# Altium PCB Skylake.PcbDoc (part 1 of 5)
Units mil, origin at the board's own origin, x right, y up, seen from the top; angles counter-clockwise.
Board outline 4000 x 4000 mil, 8 copper layers (TOP LAYER, GND1#2, SIG1#3, SIG2#4, GND2#5, SIG3#6, GND3#7, BOTTOM LAYER), stack 132.6 mil thick; 343 components, 142 nets, 972 pads, 752 vias.
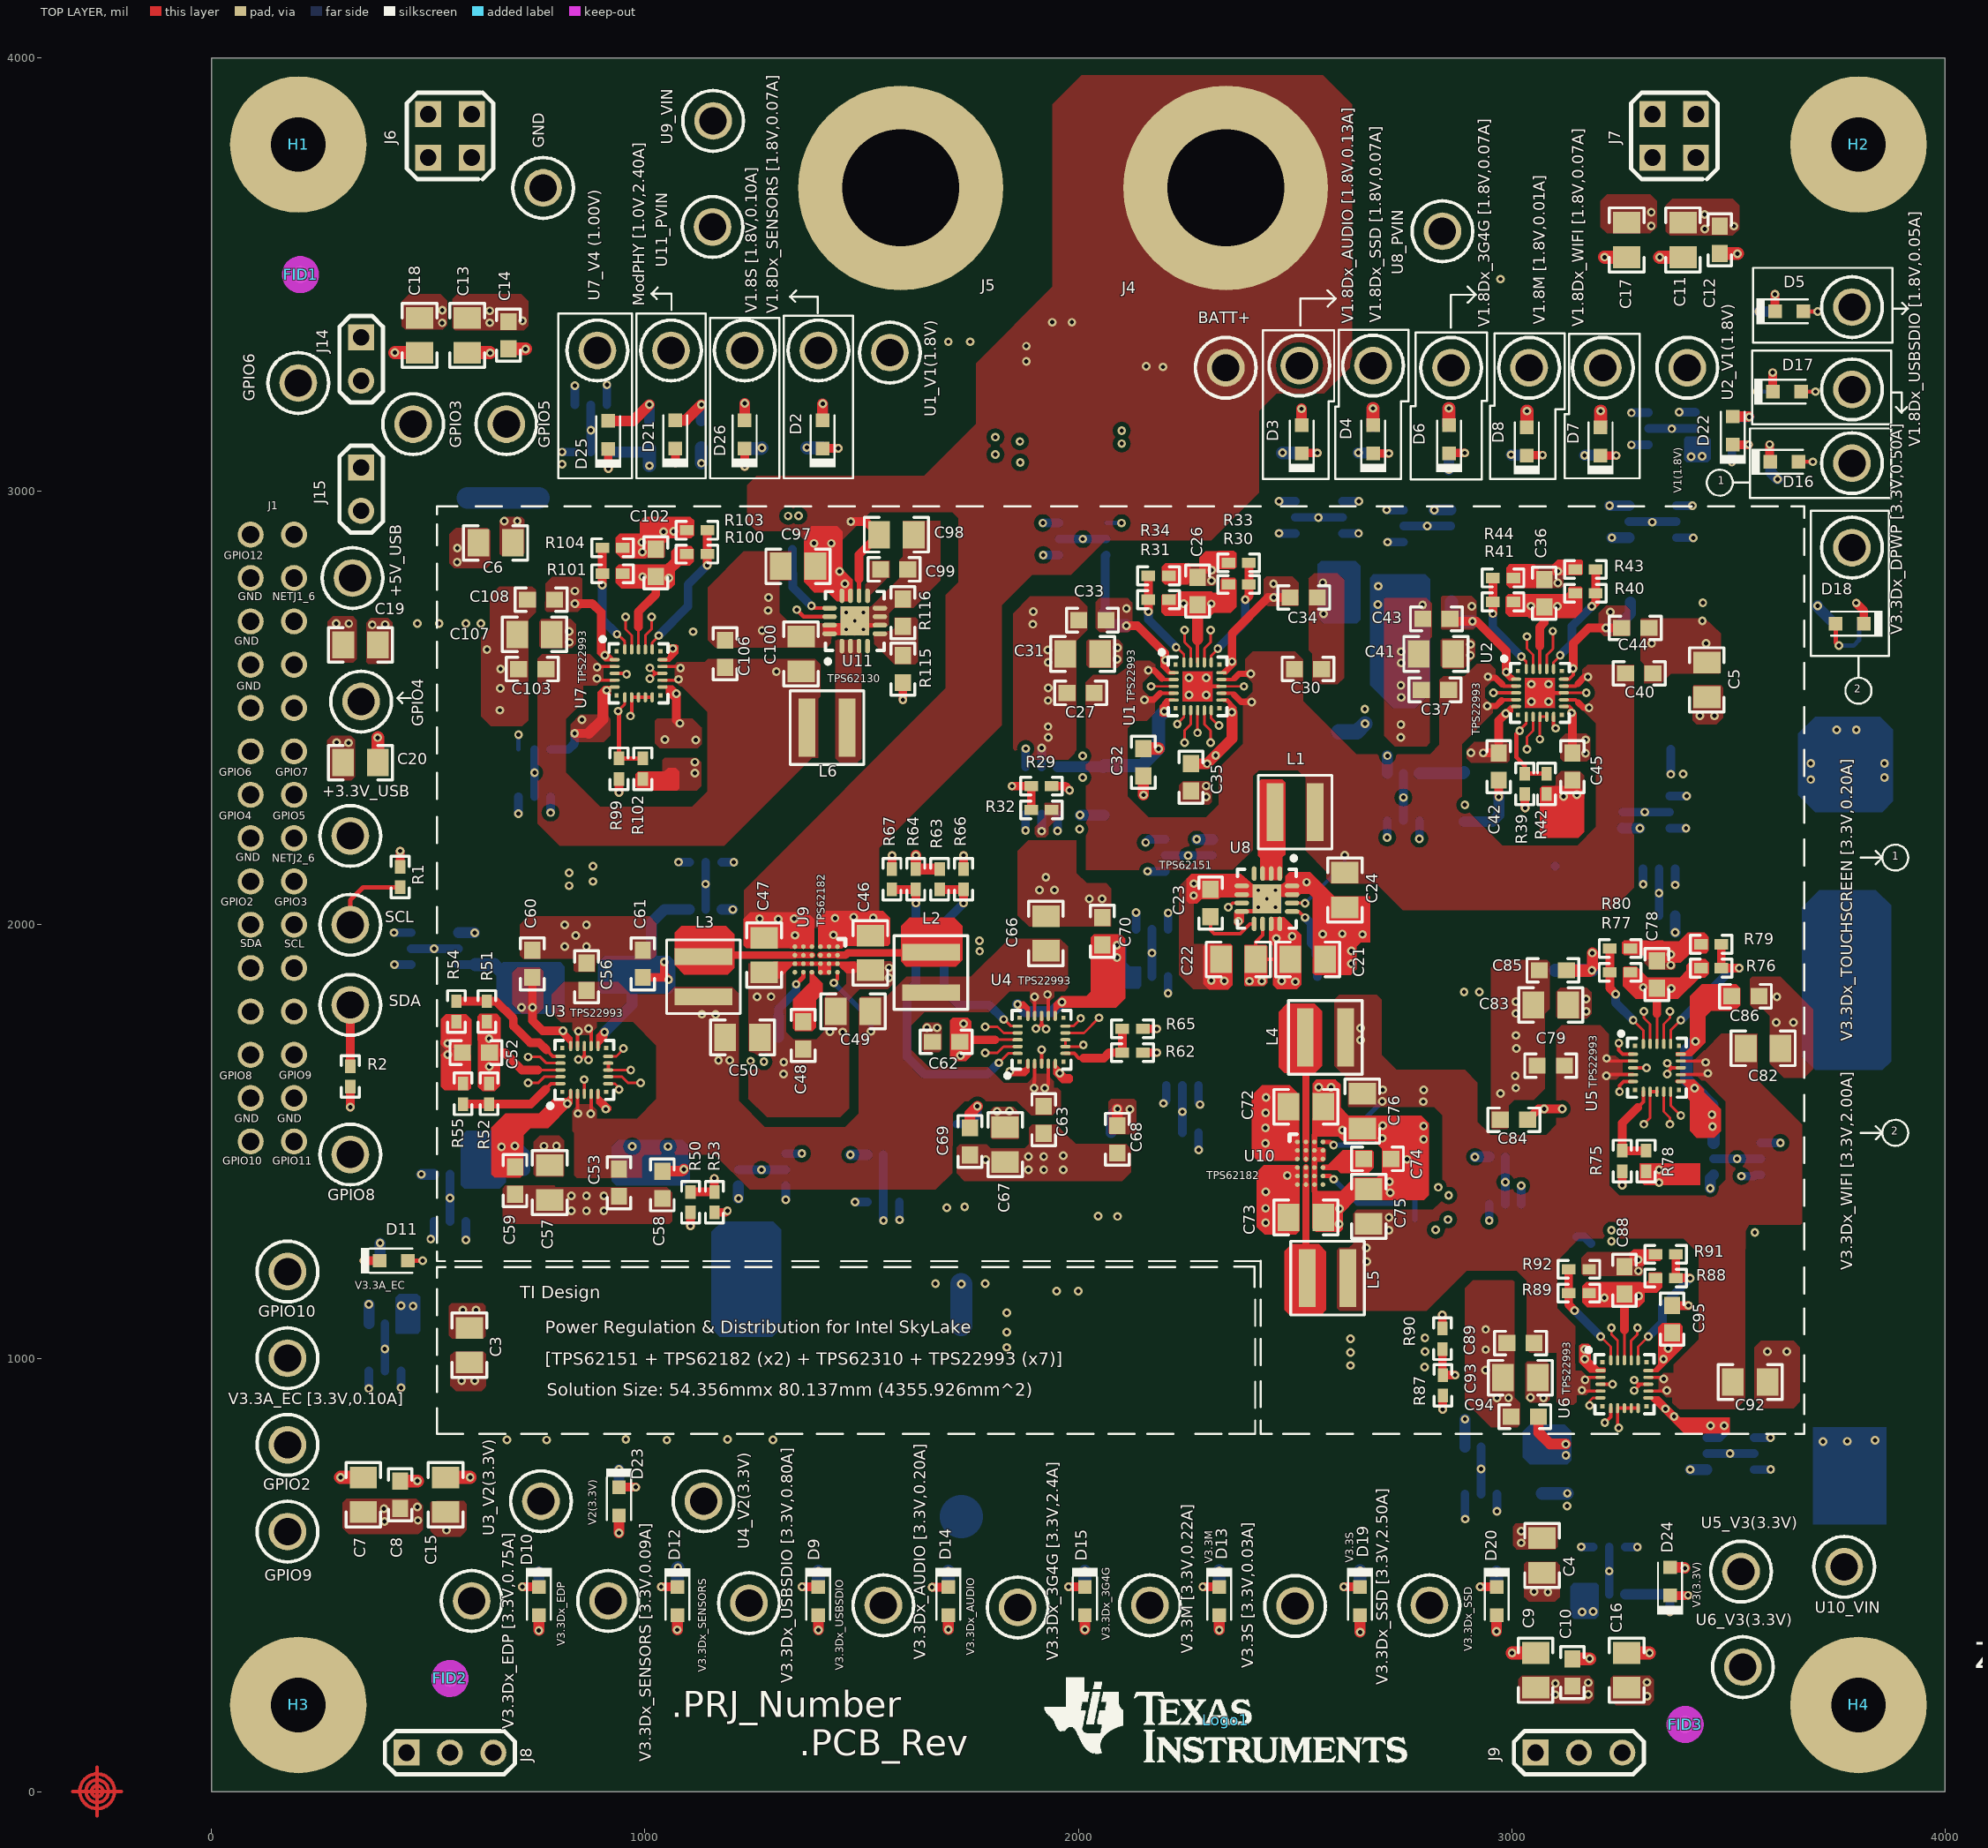
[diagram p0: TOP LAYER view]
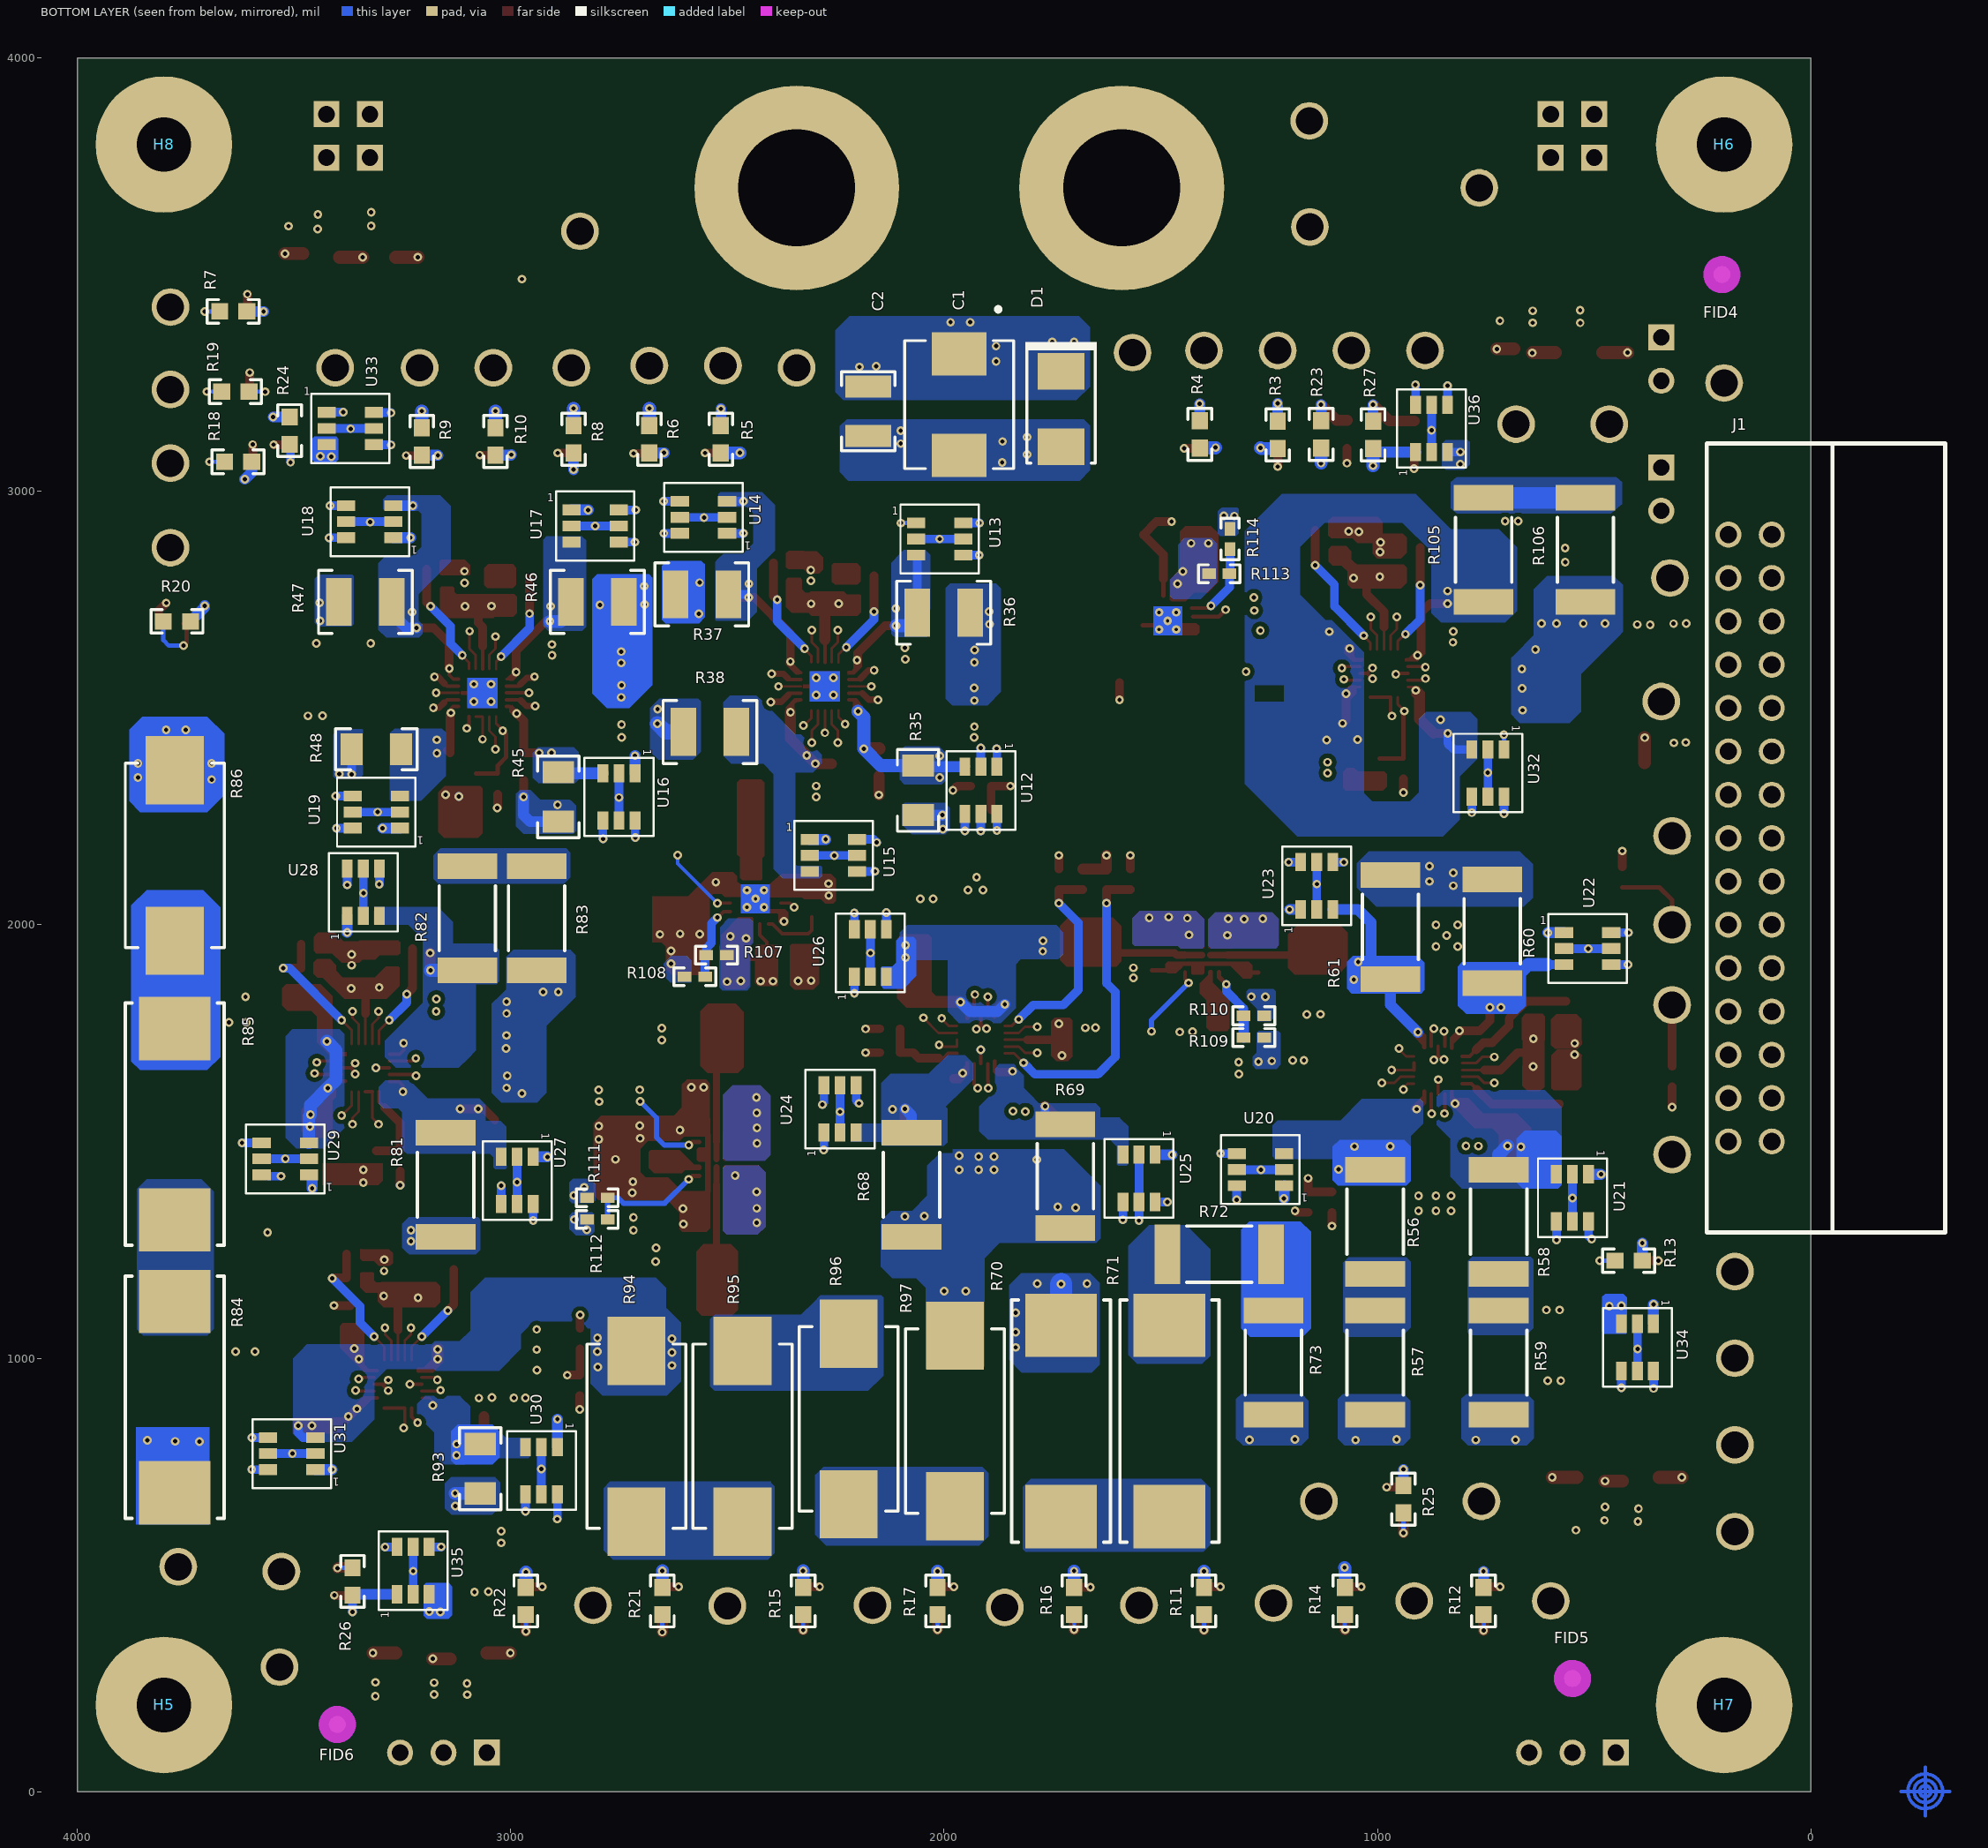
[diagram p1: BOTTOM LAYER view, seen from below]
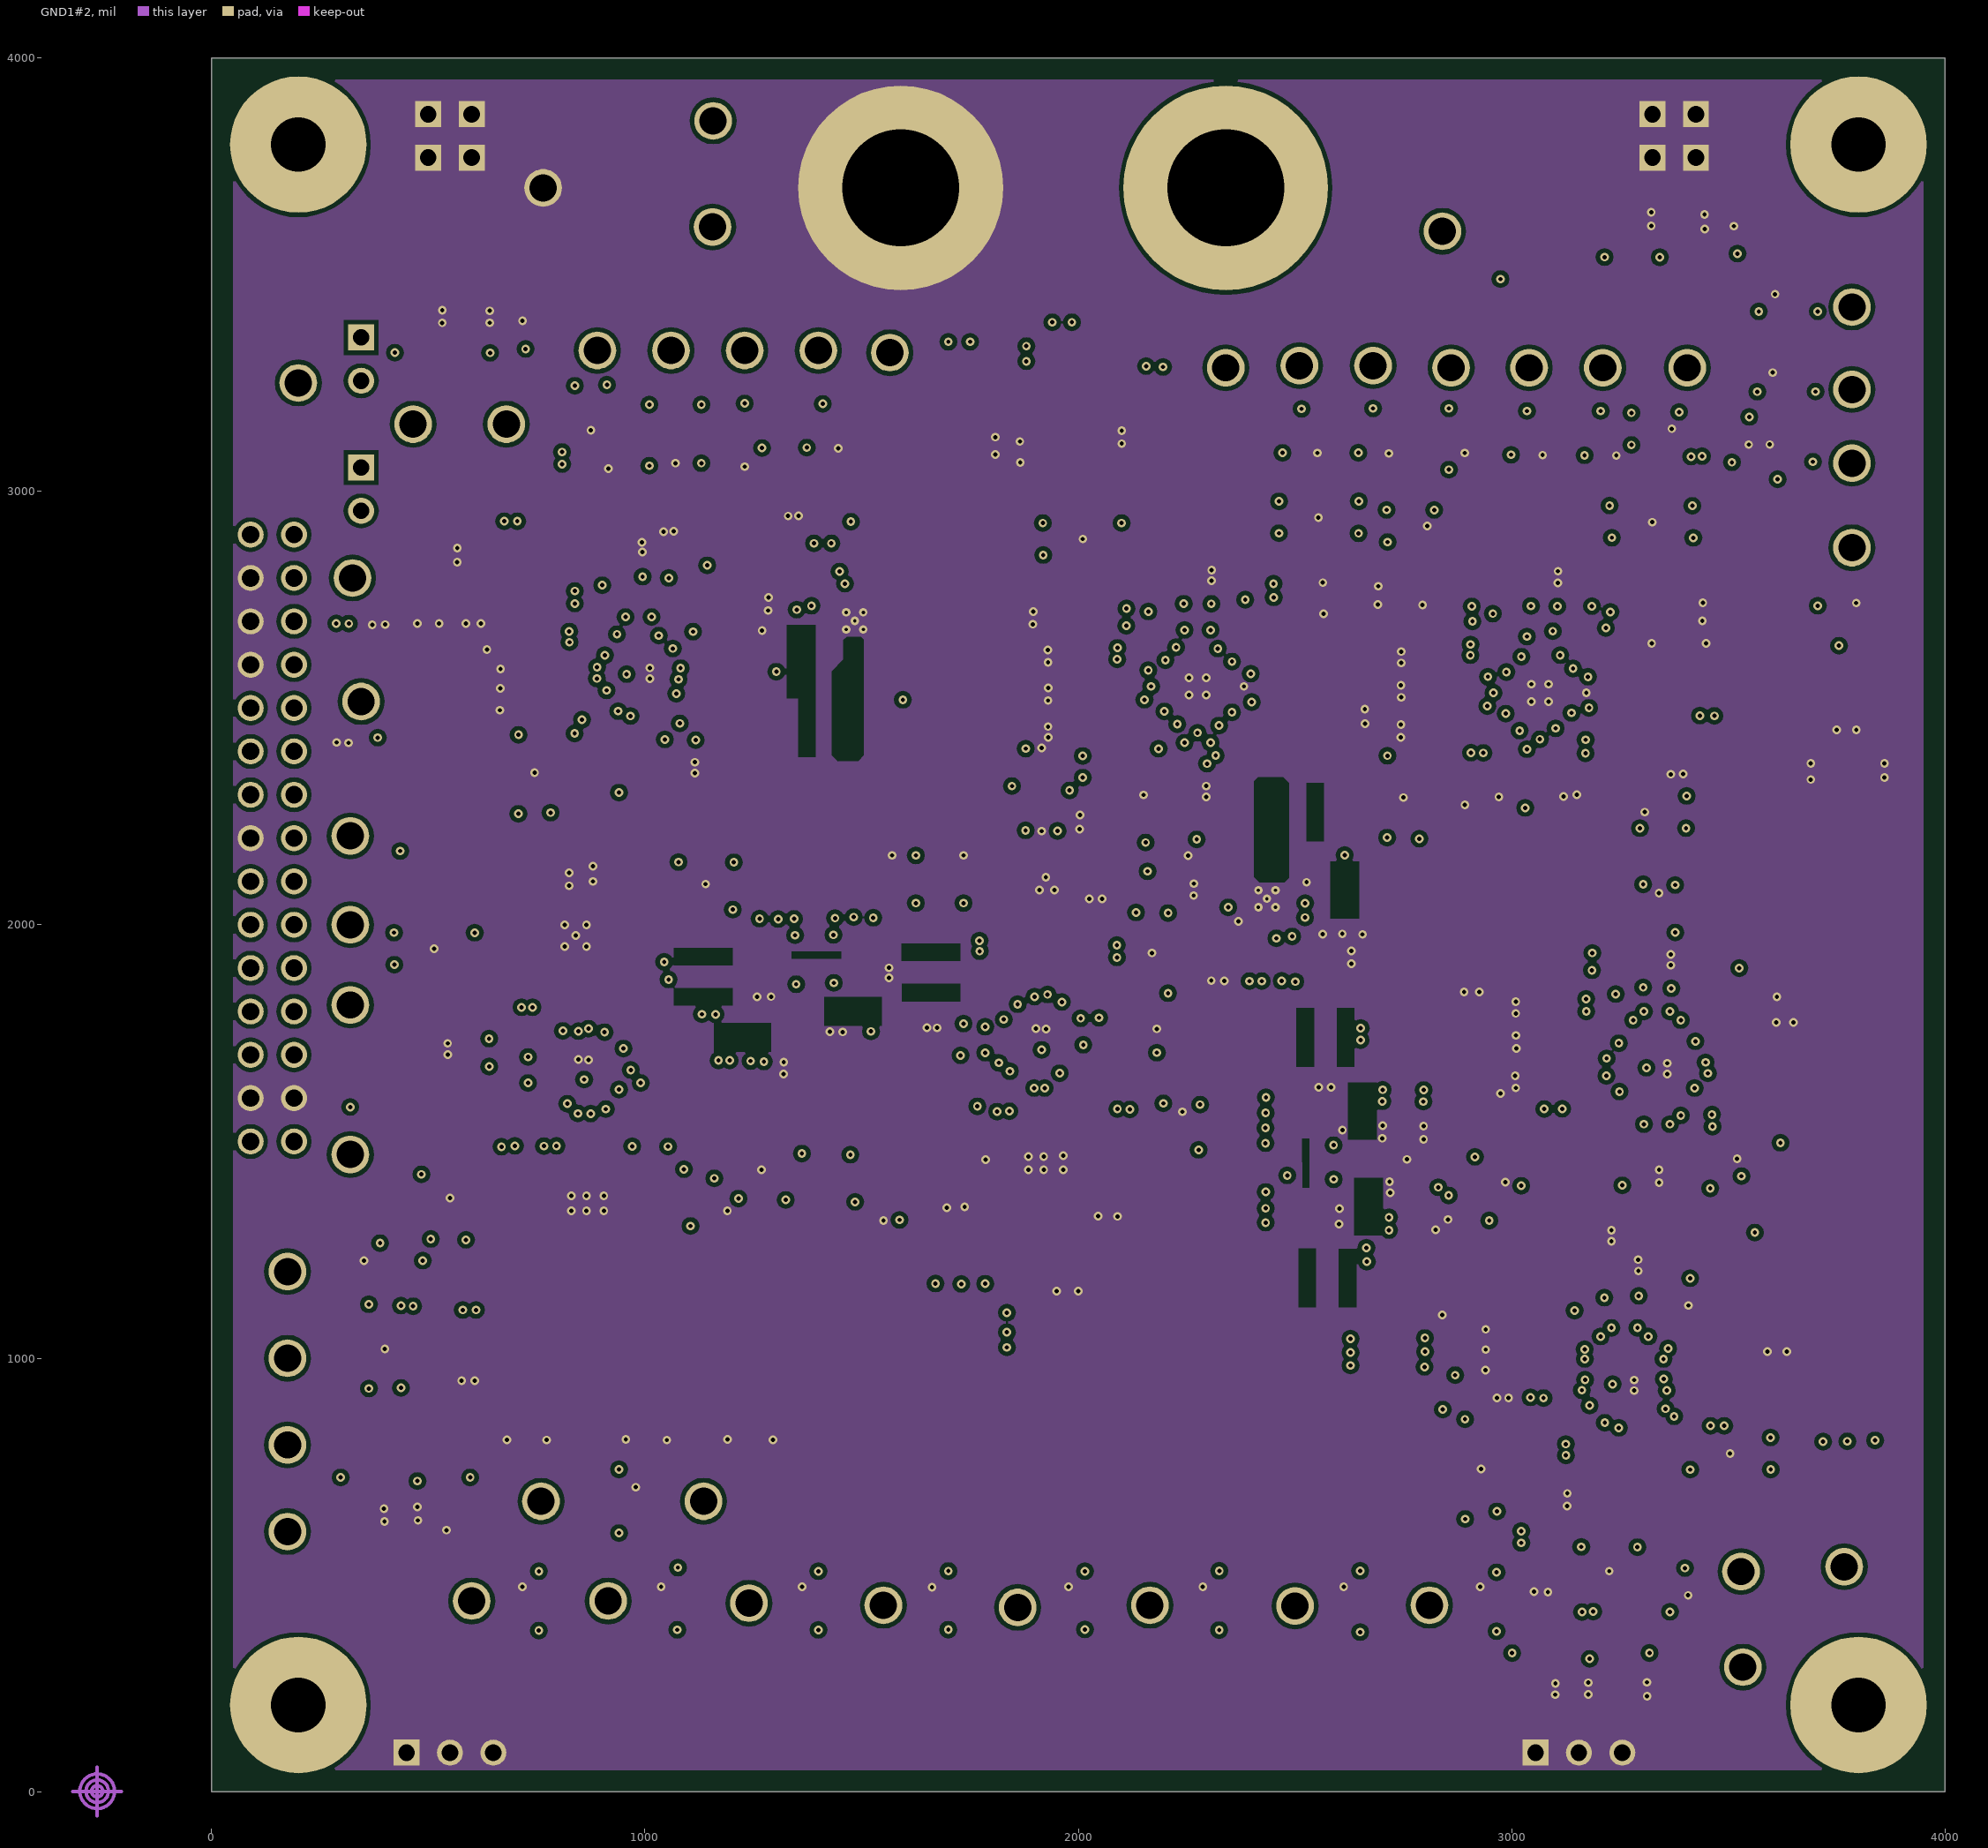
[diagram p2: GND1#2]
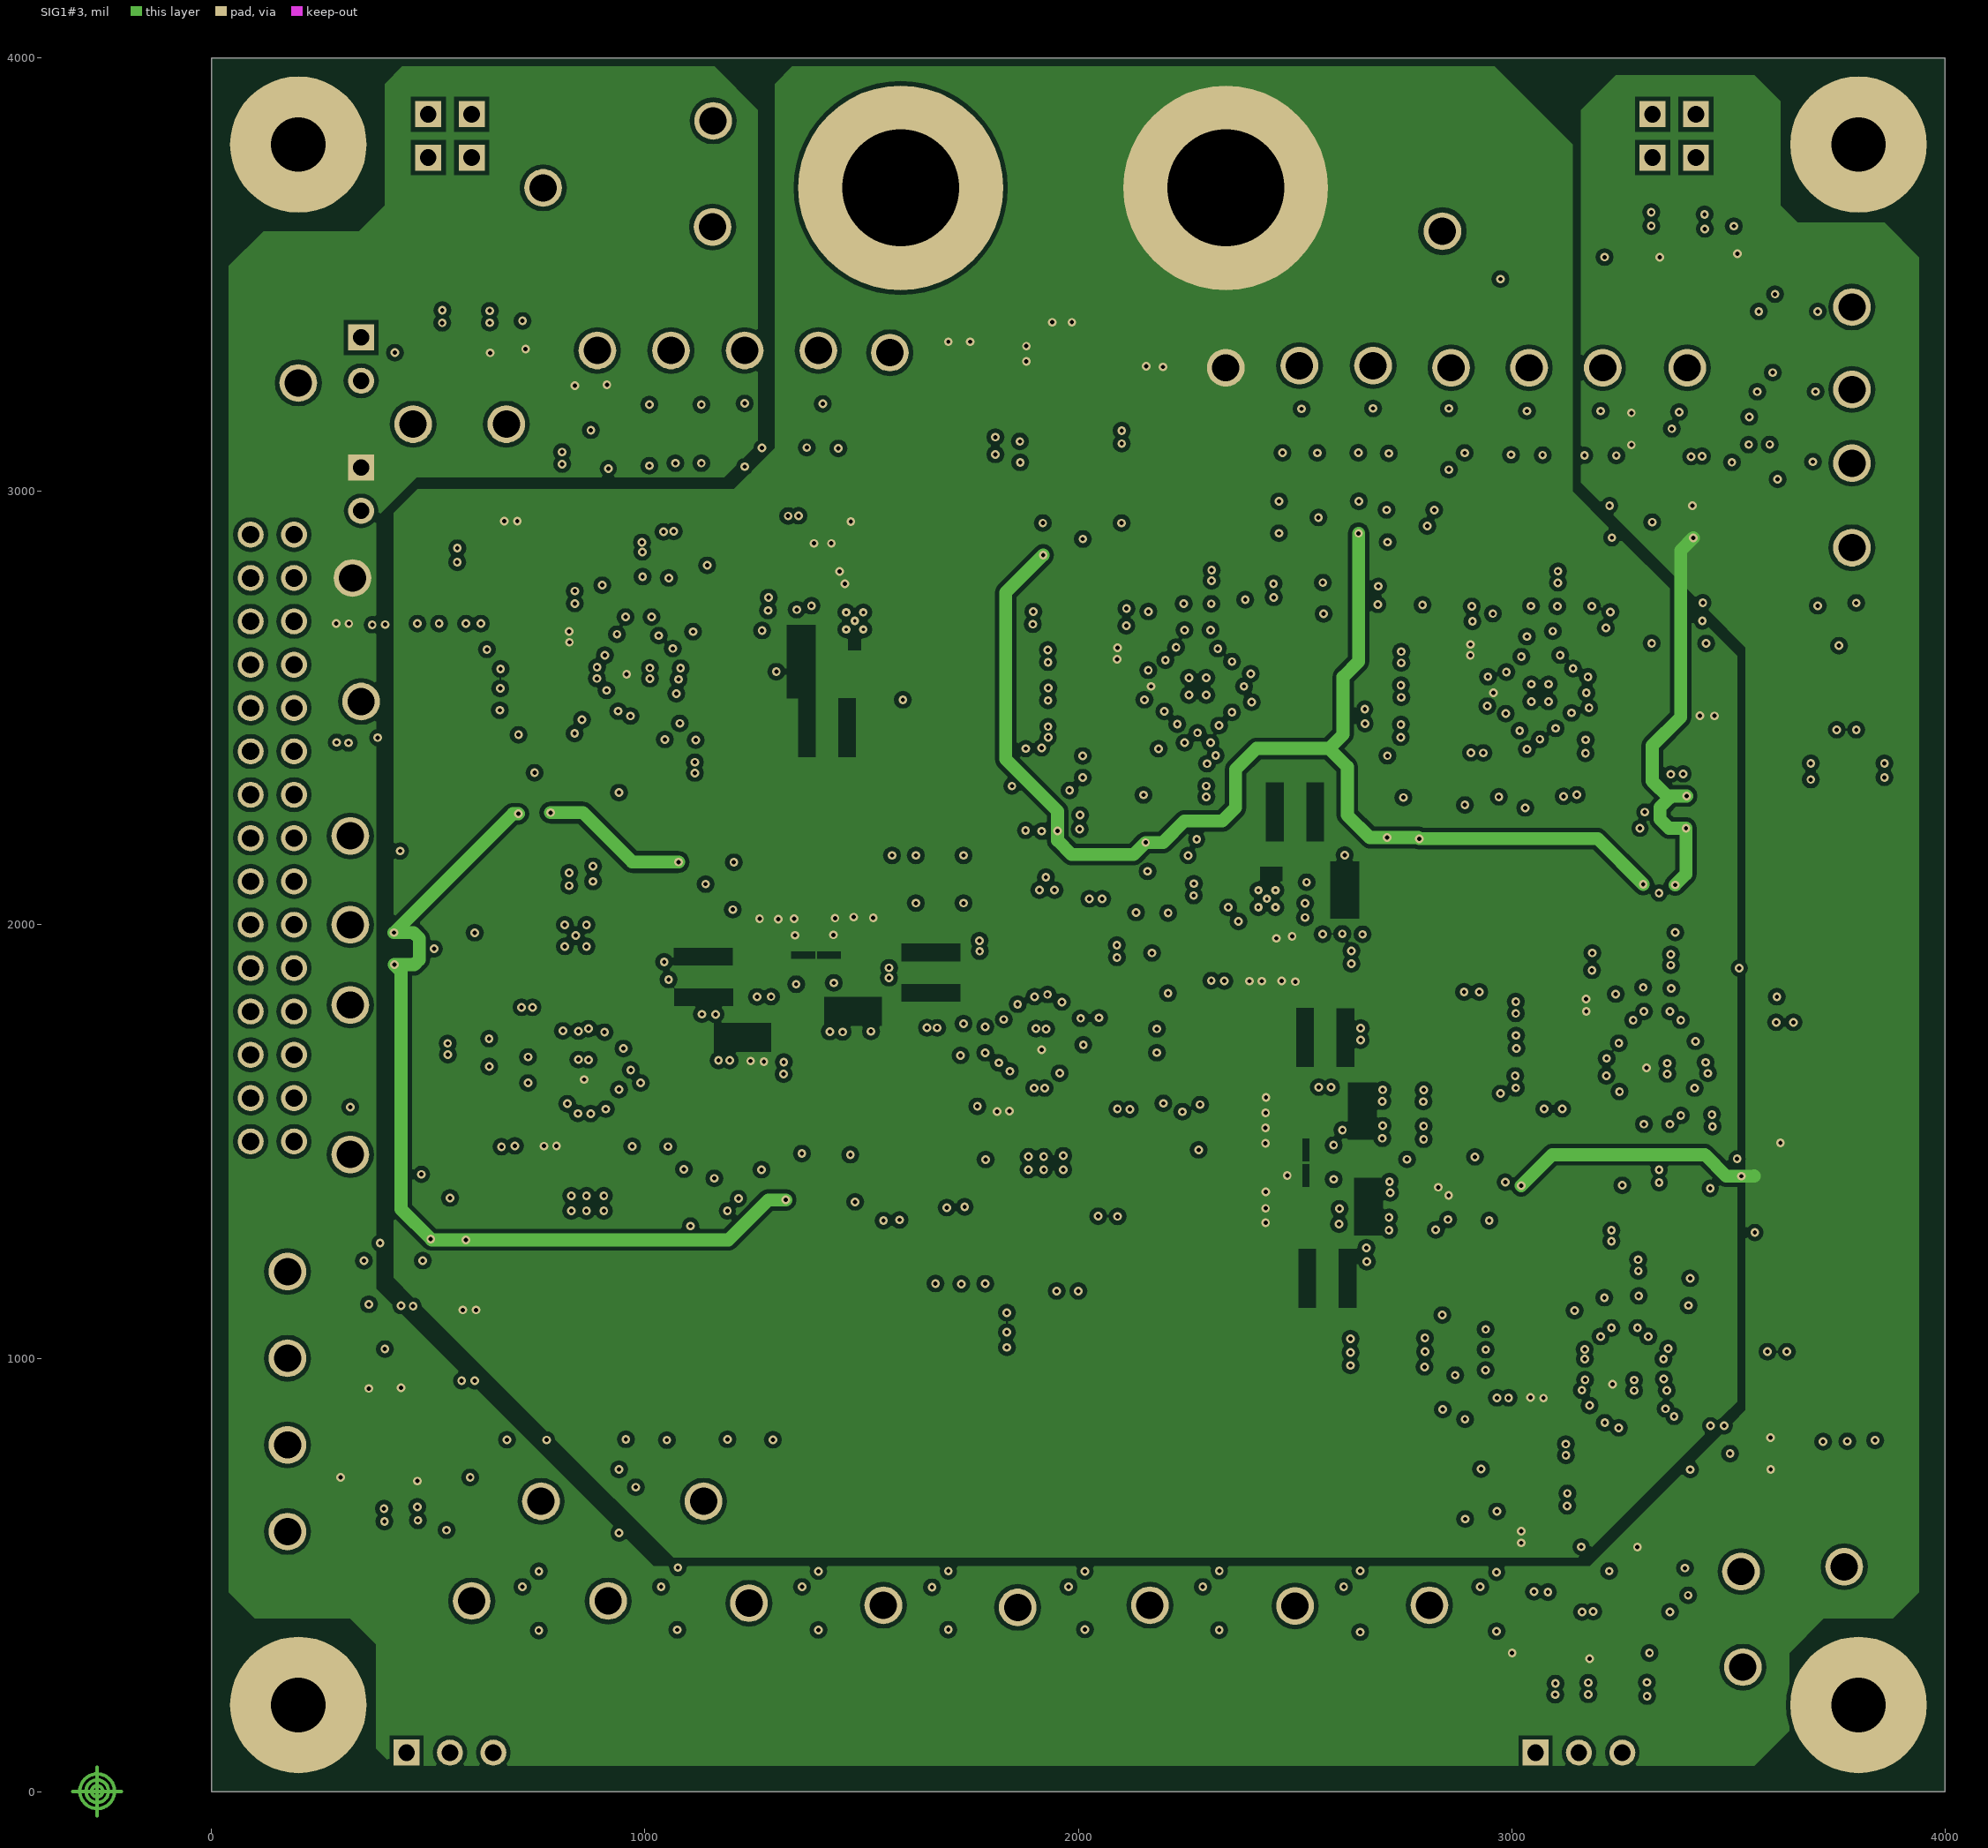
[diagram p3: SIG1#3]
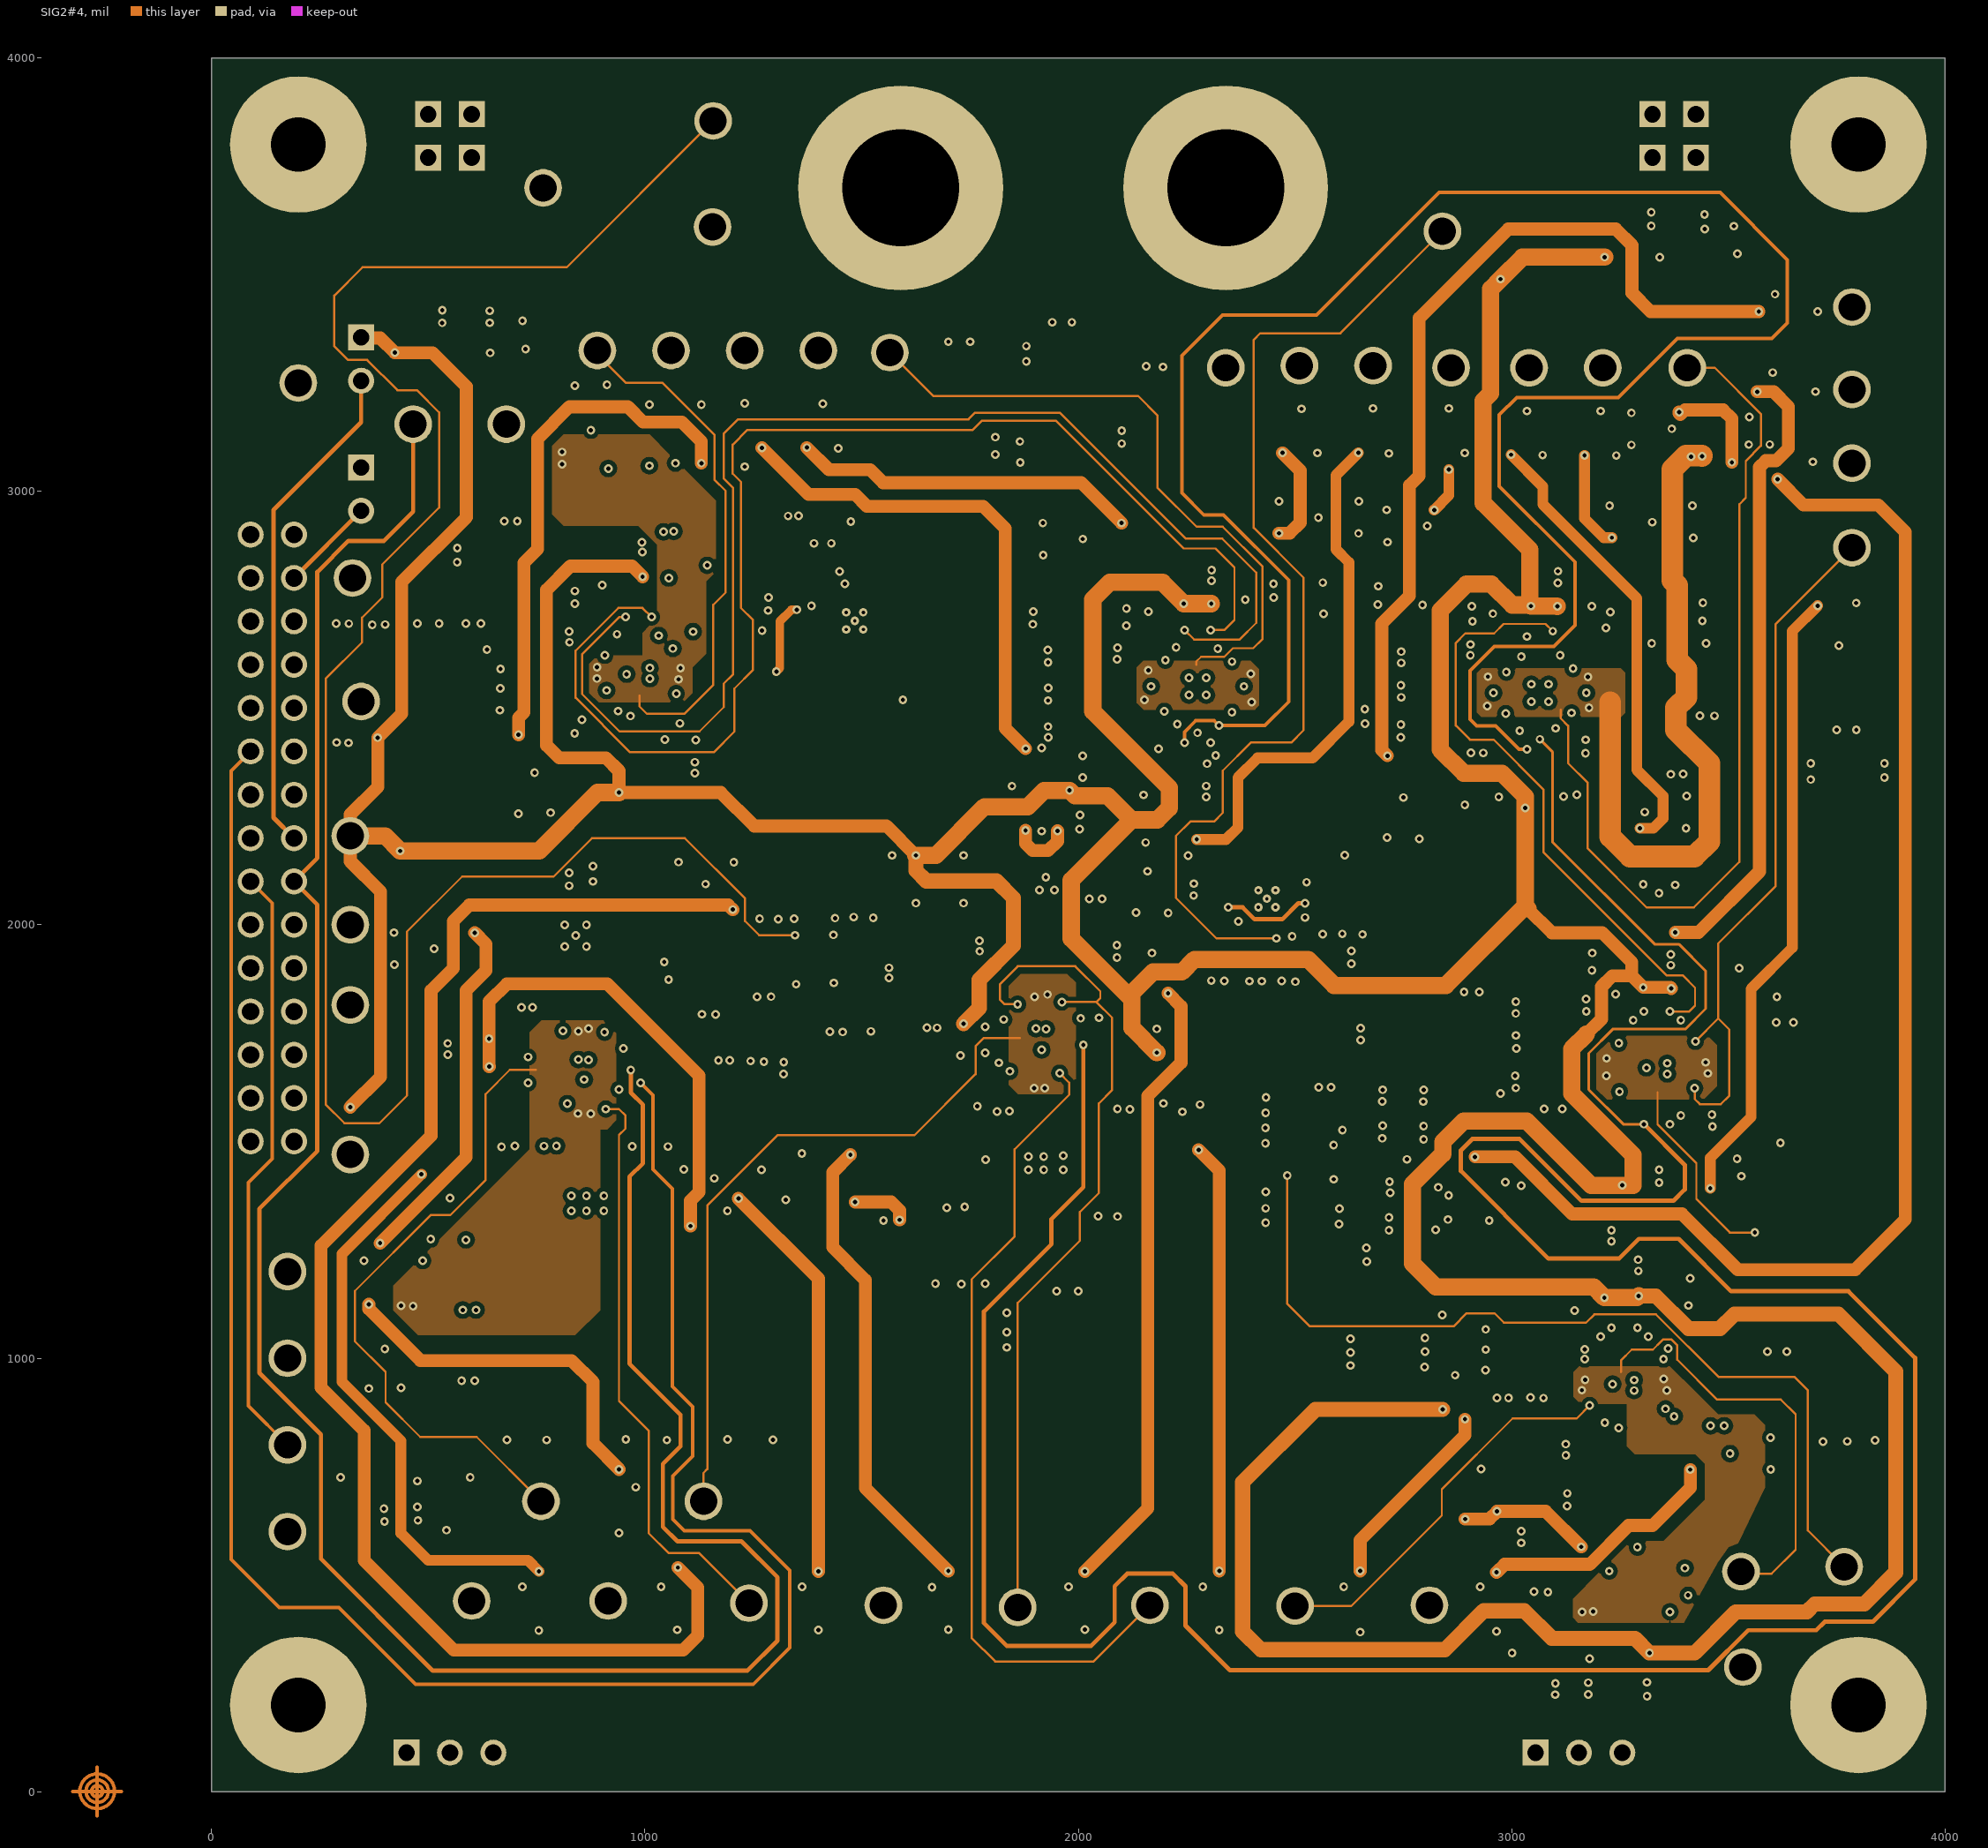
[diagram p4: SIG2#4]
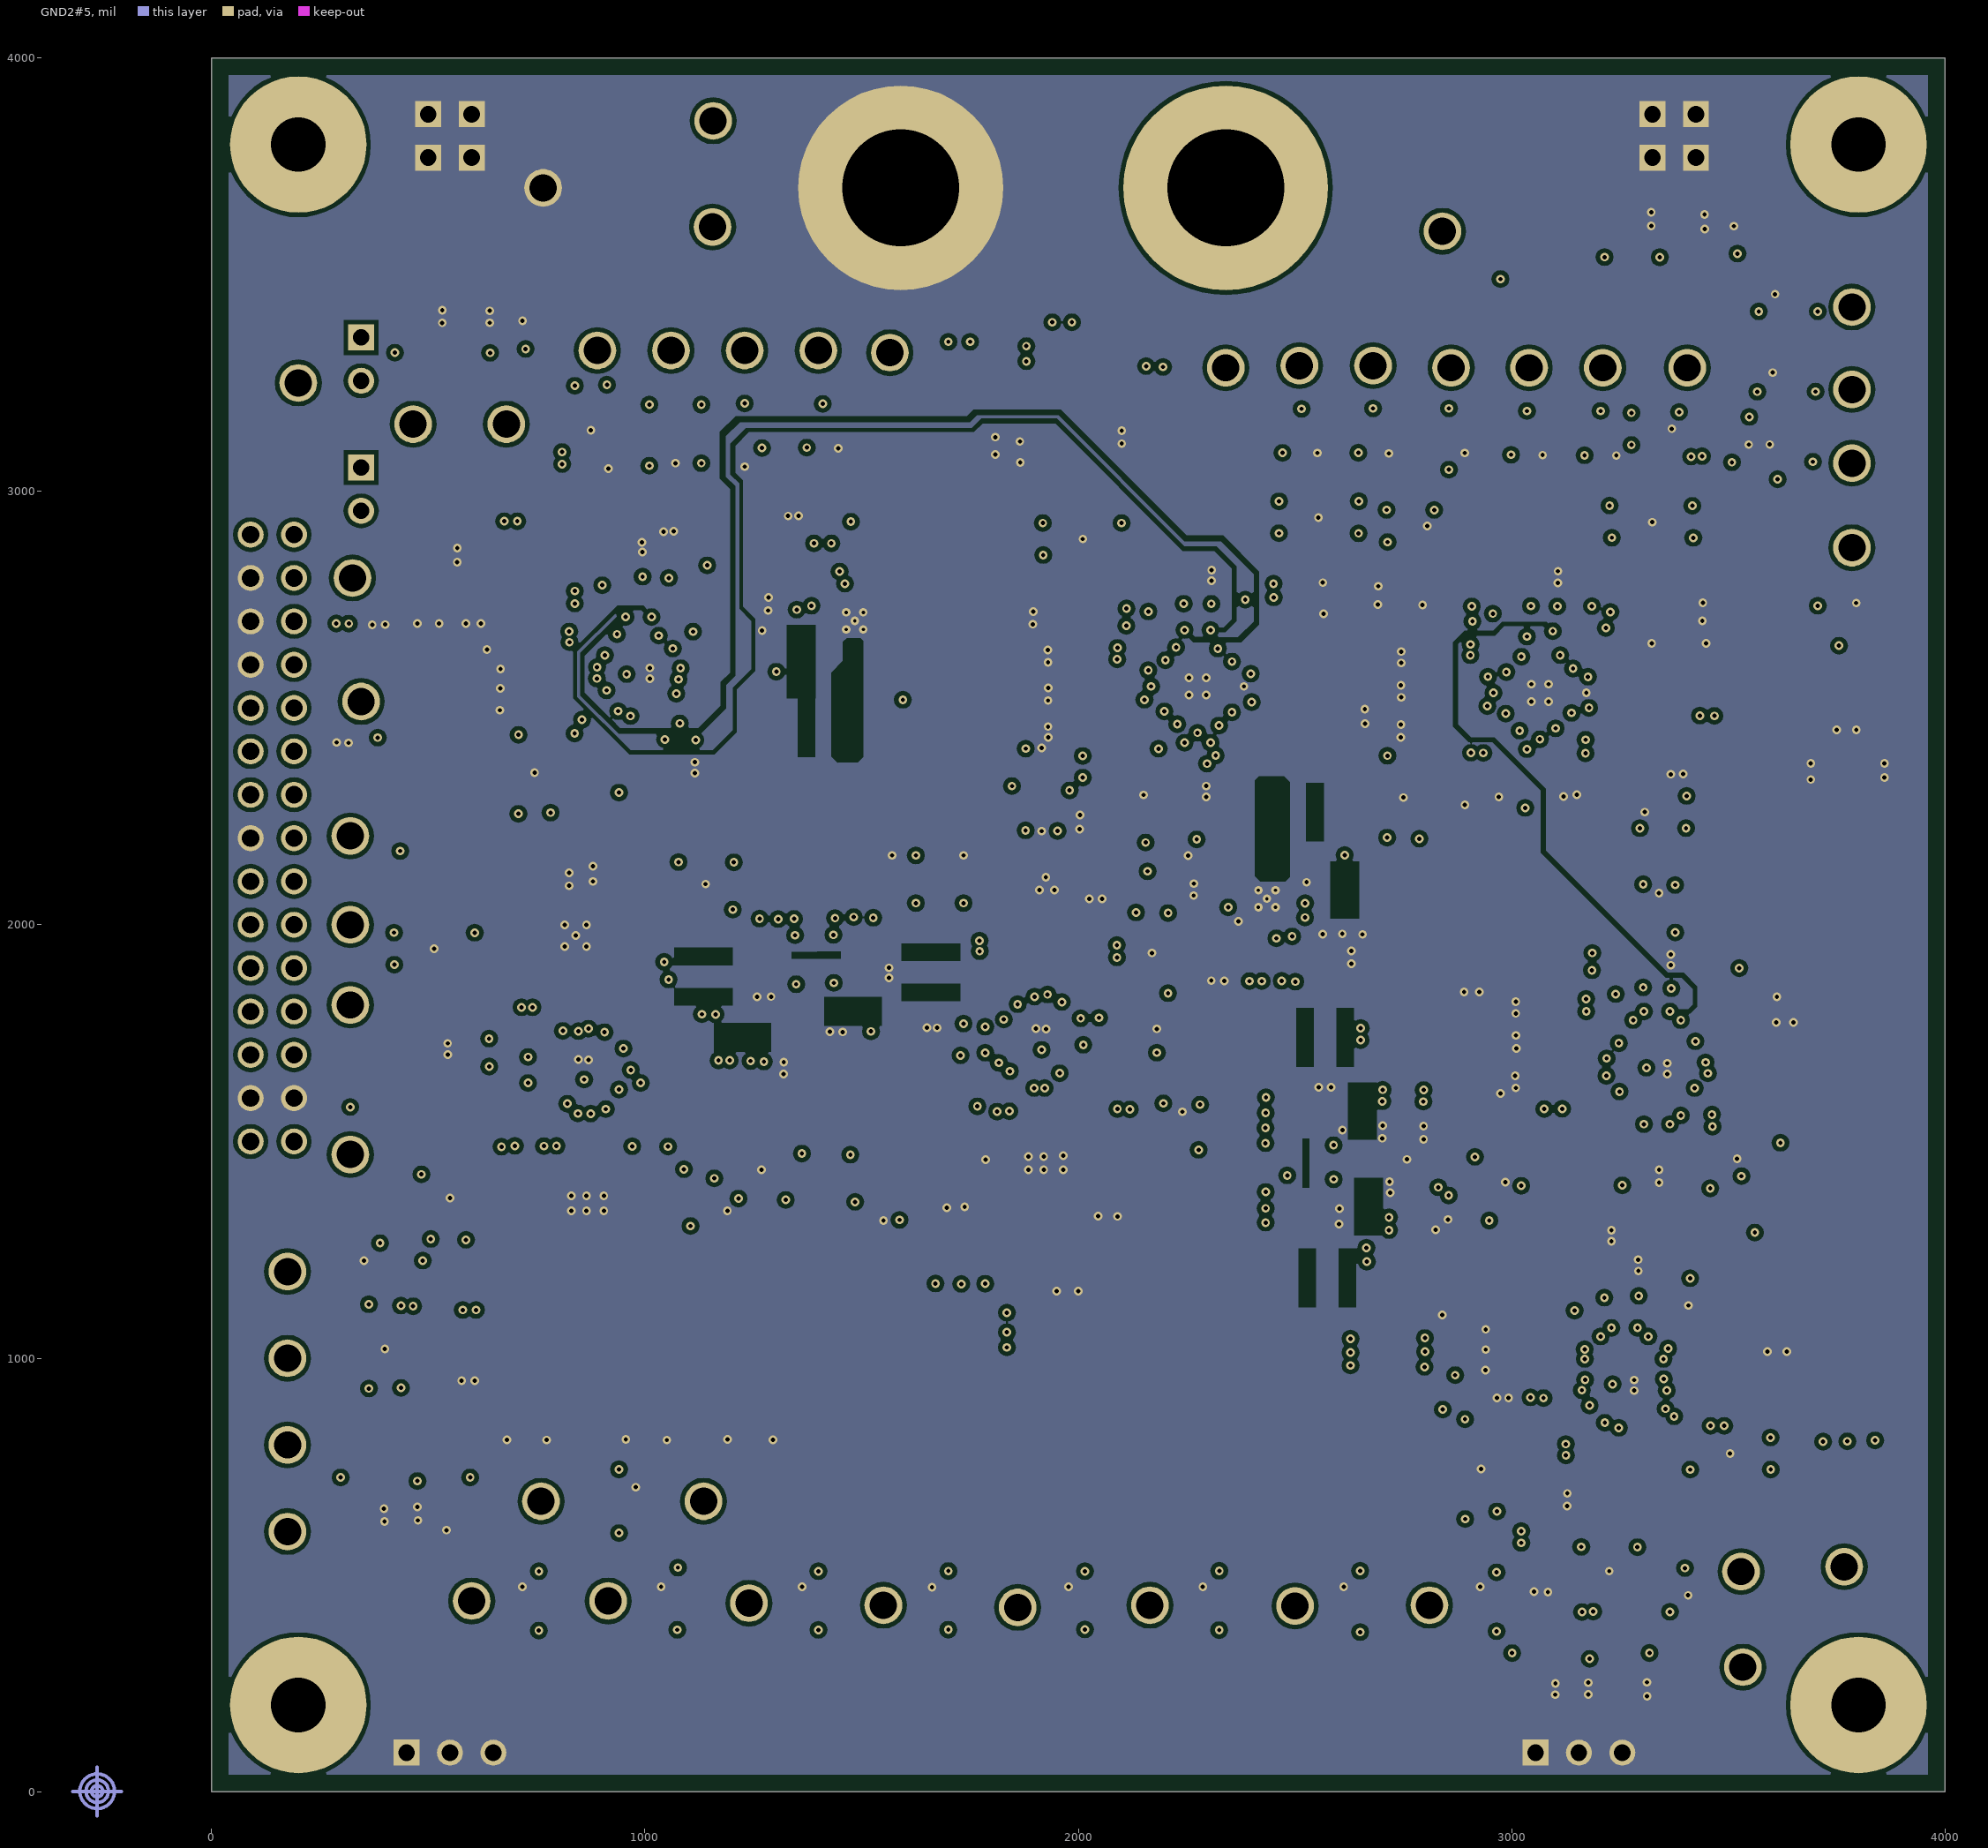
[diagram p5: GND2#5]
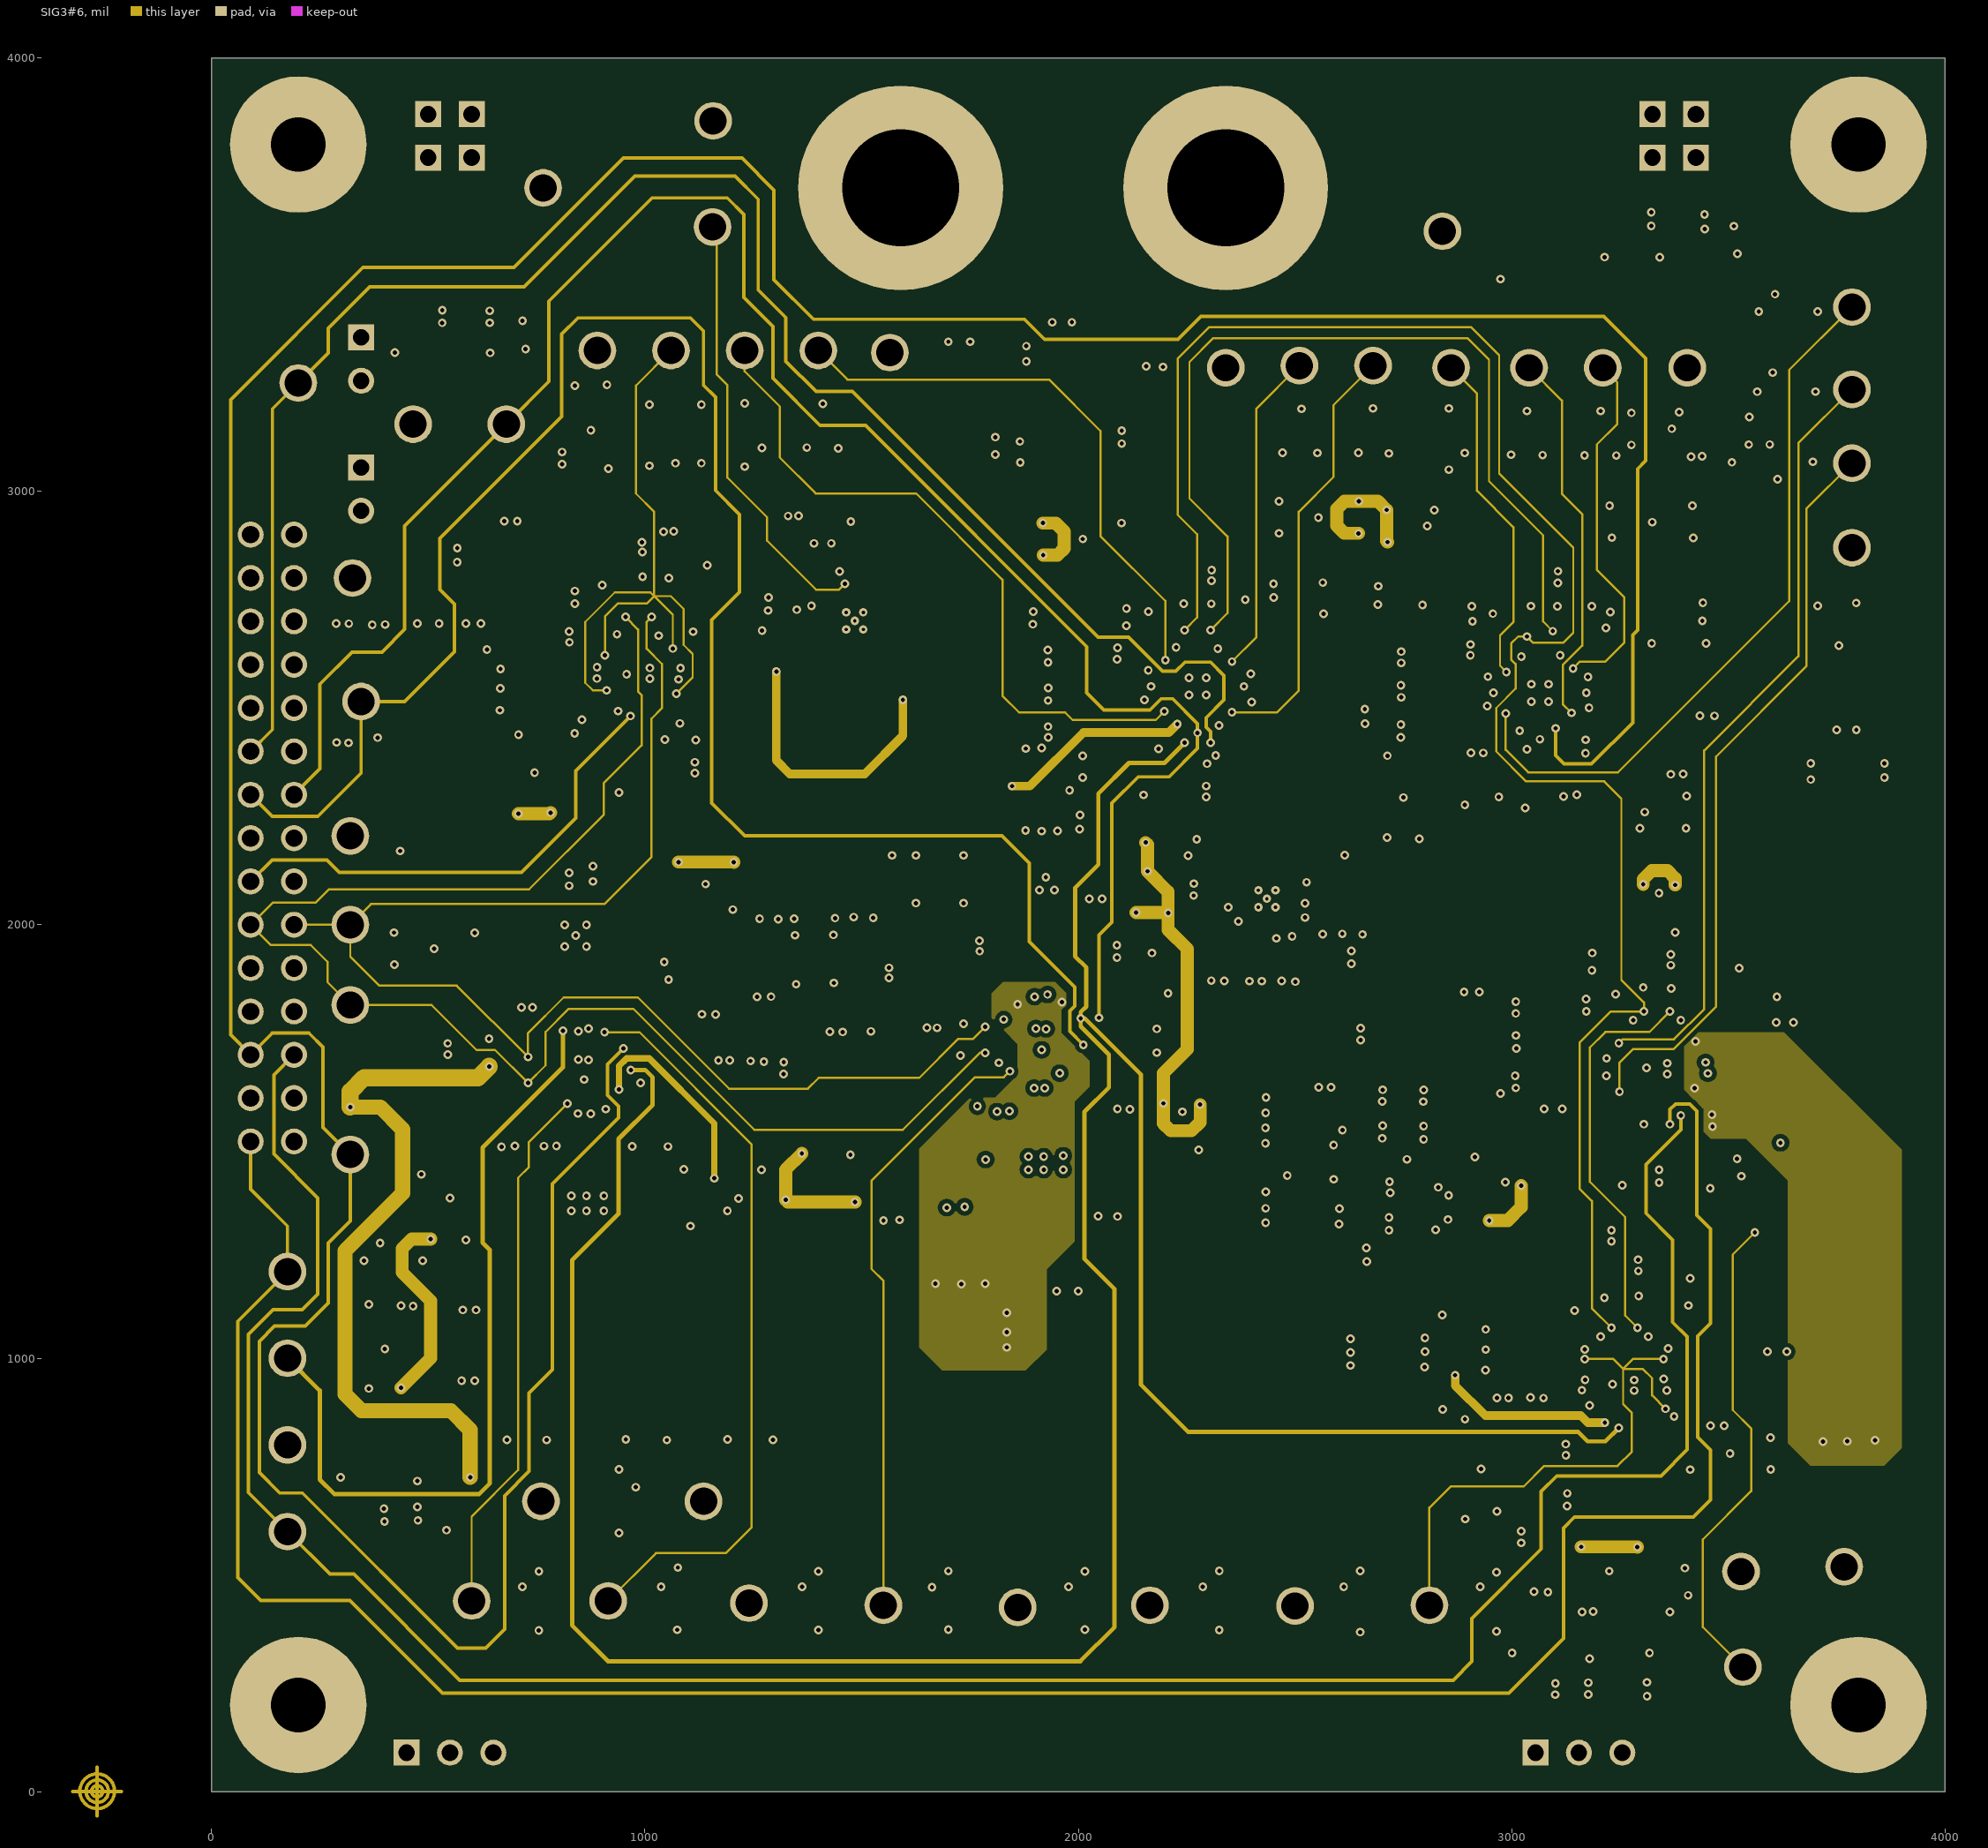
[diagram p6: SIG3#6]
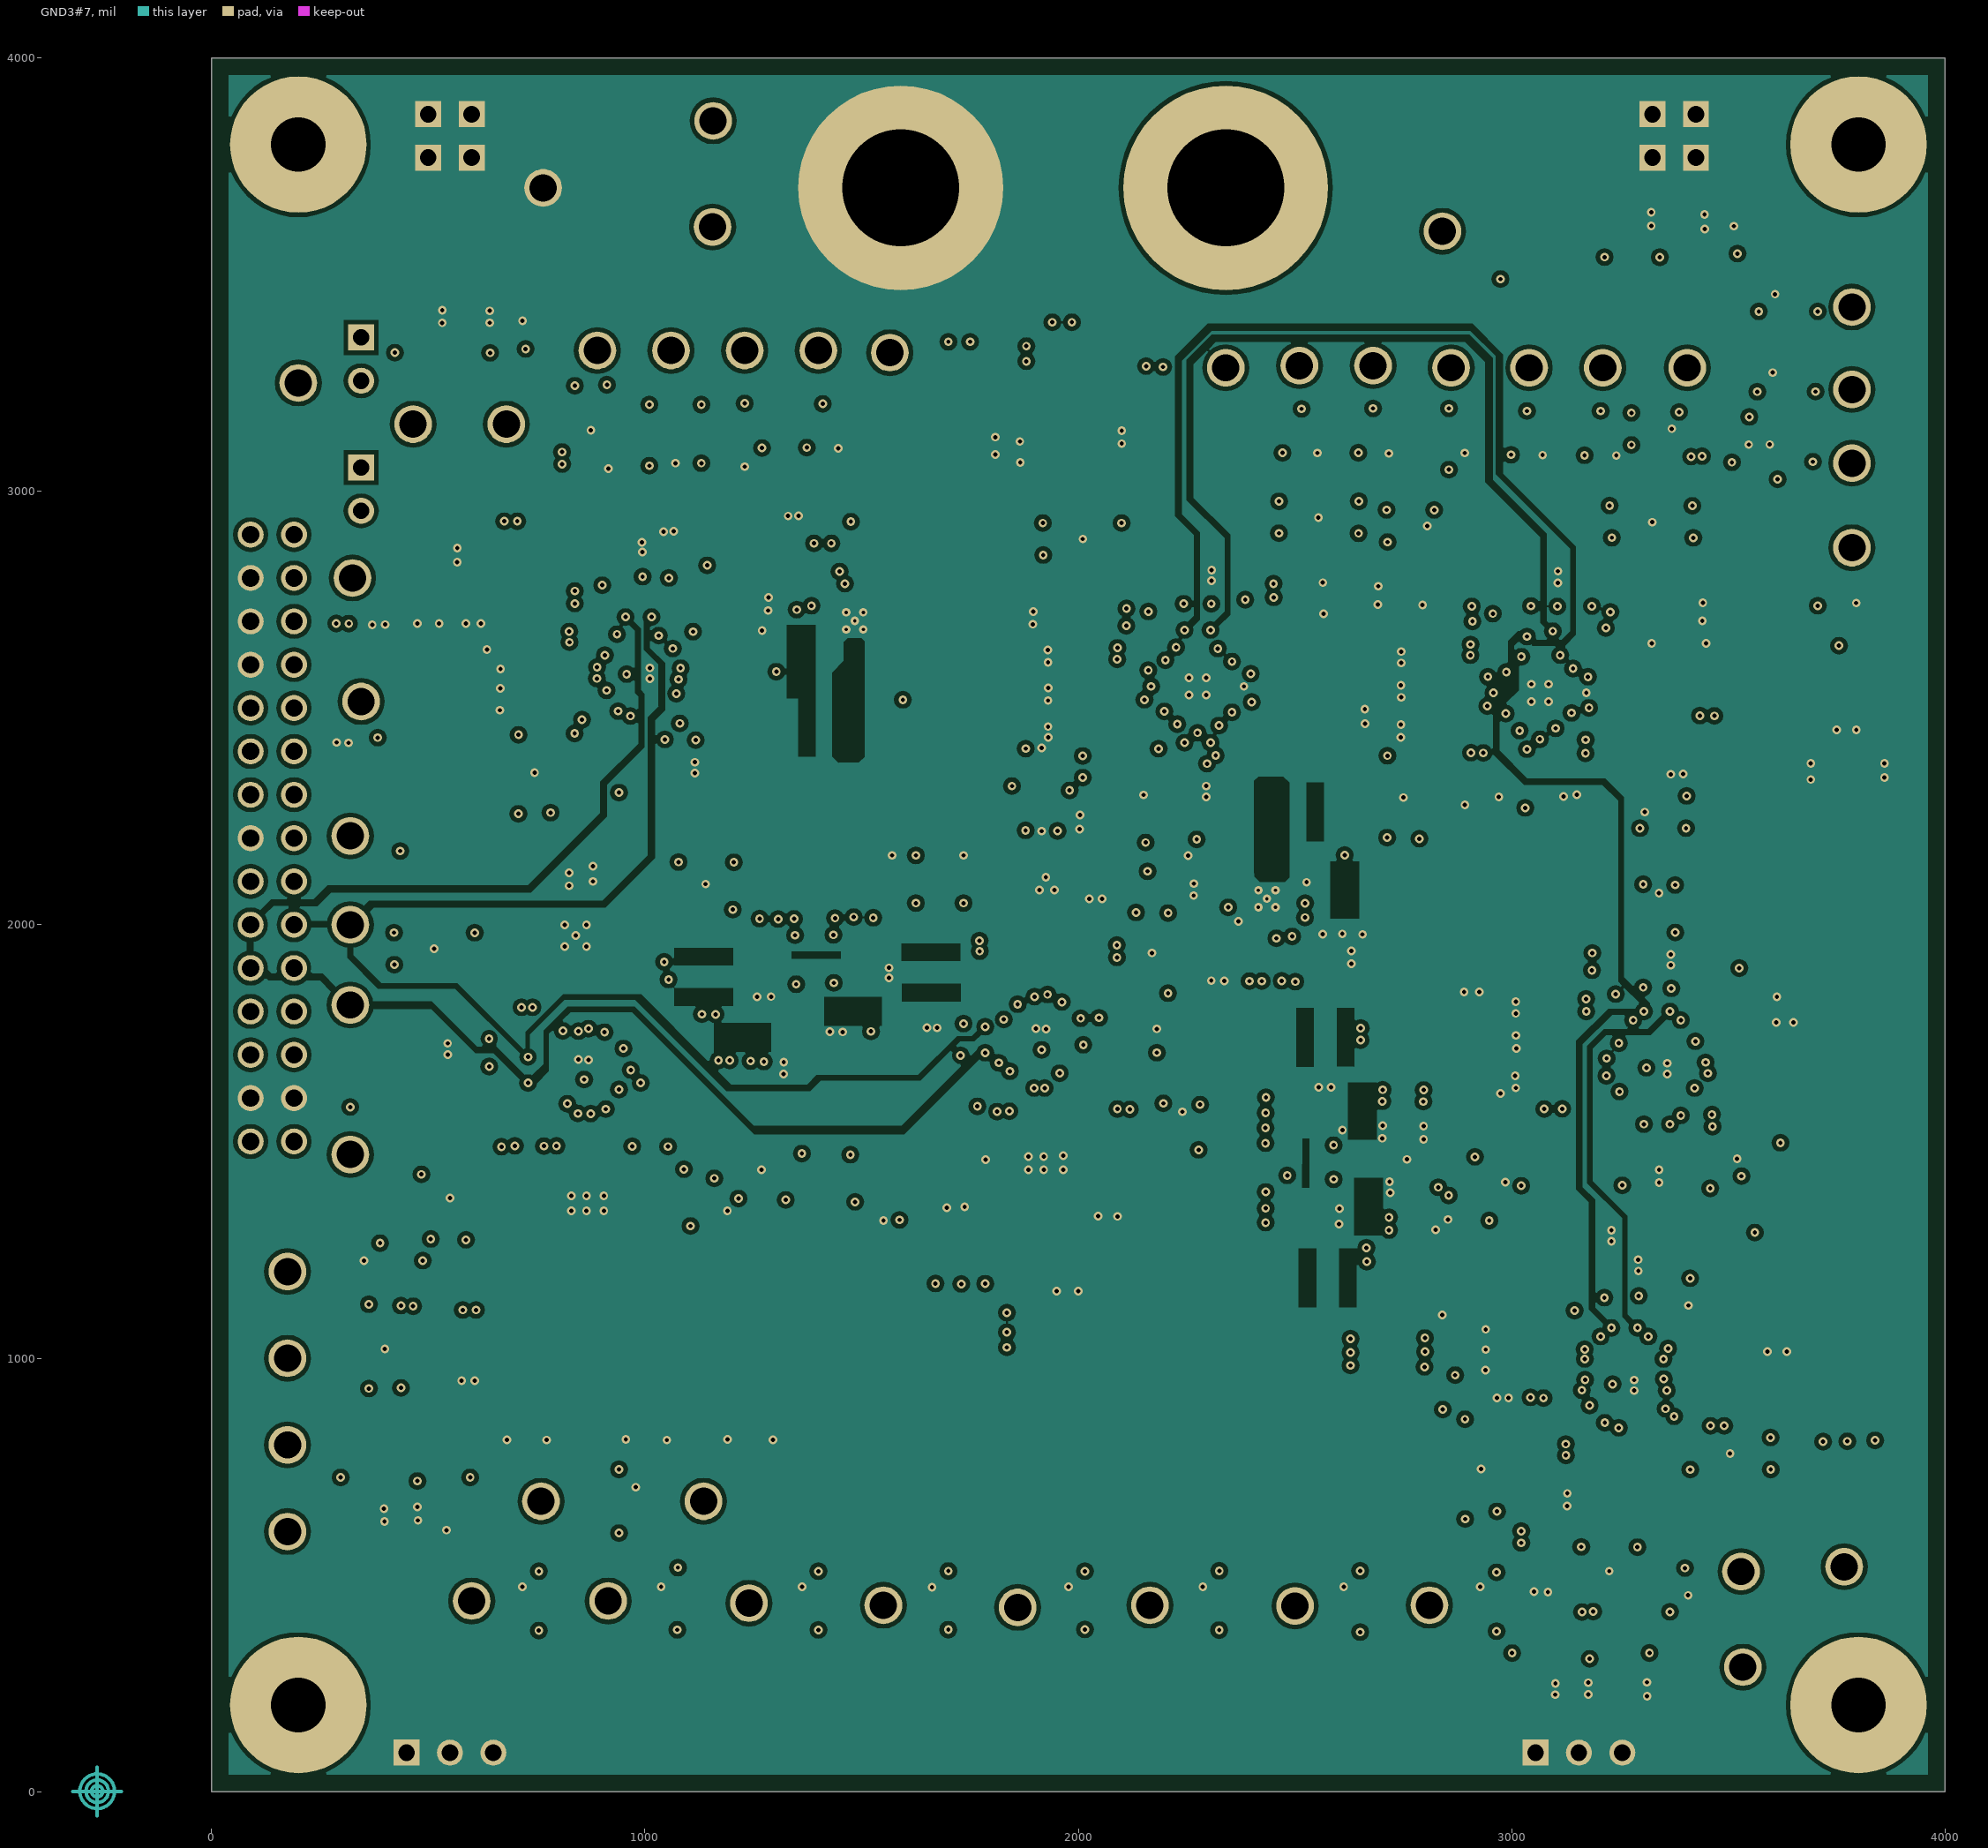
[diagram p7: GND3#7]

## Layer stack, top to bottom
Top Solder: solder mask 0.4, Solder Resist, Dk 3.5
TOP LAYER: signal copper 2.8
Dielectric1: core 59.2, FR-4, Dk 4.8
GND1#2: signal copper 2.8
Dielectric2: prepreg 12.6, FR-4, Dk 4.8
SIG1#3: signal copper 1.4
Dielectric3: core 12.6, FR-4, Dk 4.8
SIG2#4: signal copper 1.4
Dielectric4: prepreg 5, FR-4, Dk 4.2
GND2#5: signal copper 2.8
Dielectric5: core 5, FR-4, Dk 4.2
SIG3#6: signal copper 1.4
Dielectric6: prepreg 10, FR-4, Dk 4.2
GND3#7: signal copper 2.8
Dielectric7: core 10, FR-4, Dk 4.2
BOTTOM LAYER: signal copper 2.8
Bottom Solder: solder mask 0.4, Solder Resist, Dk 3.5

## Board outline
0,0 4000,0 4000,4000 0,4000

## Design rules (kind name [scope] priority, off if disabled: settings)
AcuteAngle [All] p1: minimum=4.50000000000000E+0001 checktracksonly=FALSE
AssemblyTestPointUsage [All] p1: valid=2
Clearance Clearance_BoardEdge_MountingHoles [OnCopper and InComponentClass('Mounting Holes') vs IsKeepOut] p1: gap=40
Clearance Clearance_BoardEdge_Poly [OnCopper and InPoly vs IsKeepOut] p2: gap=25
Clearance Clearance_BoardEdge [OnCopper and Not InComponentClass('Logo') and not InComponentClass('FiducialMark') and not InRegion(1000,500,4000,800) and Not IsKeepout vs IsKeepOut] p3: gap=70
Clearance Clearance_Poly [InPolygon] p4: gap=10
Clearance [All] p5: gap=3
ComponentClearance ComponentClearance_Shunt [InComponentClass('Header') vs InComponentClass('Shunt')] p1: gap=0 collisioncheckmode=3 verticalgap=0 showdistances=FALSE
ComponentClearance ComponentClearance_Logo [InComponentClass('Logo')] p2: gap=5 collisioncheckmode=3 verticalgap=10 showdistances=FALSE
ComponentClearance ComponentClearance_ScrewToNut [(HasFootprint('NY PMS 440 0025 PH')) vs (HasFootprint('Keystone_1902C'))] p3: gap=5 collisioncheckmode=3 verticalgap=10 showdistances=FALSE
ComponentClearance ComponentClearance_MountingHoles [InComponentClass('Mounting Holes')] p4: gap=25 collisioncheckmode=3 verticalgap=100000 showdistances=FALSE
ComponentClearance ComponentClearance_SmallPassives [HasFootprint('0201*') or HasFootprint('0402*') or HasFootprint('0508') or HasFootprint('0603*') or HasFootprint('0612') or HasFootprint('0805*') or HasFootprint('0815*') or HasFootprint('0830*') or HasFootprint('1206*') or HasFootprint('1210*') or HasFootprint('1808*') or HasFootprint('1812*') or HasFootprint('1825*') or HasFootprint('2010*') or HasFootprint('2220*') or HasFootprint('2225*') or HasFootprint('2512*') or HasFootprint('2728*') or HasFootprint('3518*') vs HasFootprint('0201*') or HasFootprint('0402*') or HasFootprint('0508') or HasFootprint('0603*') or HasFootprint('0612') or HasFootprint('0805*') or HasFootprint('0815*') or HasFootprint('0830*') or HasFootprint('1206*') or HasFootprint('1210*') or HasFootprint('1808*') or HasFootprint('1812*') or HasFootprint('1825*') or HasFootprint('2010*') or HasFootprint('2220*') or HasFootprint('2225*') or HasFootprint('2512*') or HasFootprint('2728*') or HasFootprint('3518*')] p5: gap=10 collisioncheckmode=3 verticalgap=10 showdistances=FALSE
ComponentClearance ComponentClearance_THtoSMT [IsThruComponent vs IsSMTComponent] p6: gap=10 collisioncheckmode=3 verticalgap=10 showdistances=FALSE
ComponentClearance ComponentClearance_THtoTH [IsThruComponent vs IsThruComponent] p7: gap=10 collisioncheckmode=3 verticalgap=10 showdistances=FALSE
ComponentClearance [All] p8: gap=10 collisioncheckmode=3 verticalgap=10 showdistances=FALSE
DiffPairsRouting [All] p1: maxlimit=100 minlimit=10 mostfreqgap=10 toplayer_minwidth=15 toplayer_maxwidth=15 toplayer_prefwidth=15 midlayer1_minwidth=15 midlayer1_maxwidth=15 midlayer1_prefwidth=15 midlayer2_minwidth=15 midlayer2_maxwidth=15 midlayer2_prefwidth=15 midlayer3_minwidth=15 midlayer3_maxwidth=15 midlayer3_prefwidth=15 midlayer4_minwidth=15 midlayer4_maxwidth=15 midlayer4_prefwidth=15 midlayer5_minwidth=15 midlayer5_maxwidth=15 midlayer5_prefwidth=15 midlayer6_minwidth=15 midlayer6_maxwidth=15 midlayer6_prefwidth=15 bottomlayer_minwidth=15 bottomlayer_maxwidth=15 bottomlayer_prefwidth=15 maxuncoupledlength=1000
FabricationTestPointUsage TestPointUsage [All] p1: valid=2 allowmultiple=FALSE
FabricationTestpoint Testpoint [All] p1: side=3 testpointundercomponent=TRUE minsize=40 maxsize=100 preferedsize=60 minholesize=0 maxholesize=40 preferedholesize=32 testpointgrid=1 allowsidetop=TRUE allowsidebottom=TRUE usegrid=TRUE gridtolerance=0.01
FanoutControl Fanout_LCC [IsLCC] p1: bgadir=Out bgaviamode=Centered fanoutstyle=Auto fanoutdirection=Alternating viagrid=1 // Fanout_LCC (Default Rule)
FanoutControl Fanout_BGA [IsBGA] p2: bgadir=Out bgaviamode=Centered fanoutstyle=Auto fanoutdirection=Alternating viagrid=1 // Fanout_BGA (Default Rule)
FanoutControl Fanout_Default [All] p4: bgadir=Out bgaviamode=Centered fanoutstyle=Auto fanoutdirection=Alternating viagrid=1 // Fanout_Default (Default Rule)
FanoutControl Fanout_Small [(CompPinCount < 5)] p5: bgadir=Out bgaviamode=Centered fanoutstyle=Auto fanoutdirection=OutThenIn viagrid=1 // Fanout_Small (Default Rule)
HoleSize [All] p1: absolutevalues=TRUE maxlimit=270 minlimit=7.87 maxpercent=80.000 minpercent=20.000
MinimumAnnularRing MinimumAnnularRing_ThermalPadVias [IsVia and InAnyComponent] p1: minimumring=5.91
MinimumAnnularRing [All] p2: minimumring=5
MinimumSolderMaskSliver MinimumSolderMaskSliver_Logo [InComponentClass('Logo') vs InComponentClass('Logo')] p1: minsoldermaskwidth=0.7
MinimumSolderMaskSliver [All] p2: minsoldermaskwidth=3
PlaneConnect [All] p1: planeconnectstyle=Relief reliefexpansion=10 reliefentries=4 reliefconductorwidth=10 reliefairgap=10
PolygonConnect [All] p1: connectstyle=Direct reliefconductorwidth=10 reliefentries=4 polygonreliefangle="90 Angle" airgapwidth=10
RoutingVias ThermalPadVias [IsVia and InAnyComponent] p1: holewidth=7.87 width=19.68 viastyle="Through Hole" minholewidth=7.87 minwidth=19.68 maxholewidth=12.99 maxwidth=23.62
RoutingVias [All] p2: holewidth=10 width=20 viastyle="Through Hole" minholewidth=7.87 minwidth=20 maxholewidth=40 maxwidth=65
SMDToCorner [All] p1: distance=0
SilkToSilkClearance [All] p1: silktosilkclearance=2
SilkToSolderMaskClearance SilkscreenOverComponentPads [IsPad] p1: minsilkscreentomaskgap=5 clearancetoexposedcopper=TRUE
SolderMaskExpansion [All] p1: expansion=1.97
Width [All] p1: maxlimit=100 minlimit=5 preferedwidth=10 checkconnectedcopper=TRUE
15 further rules are at their usual default settings.

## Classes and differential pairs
component class Skylake_USB2ANY_connections: +3.3V_USB +5V_USB C19 C20 GPIO2 GPIO3 GPIO4 GPIO5 GPIO6 GPIO8 GPIO9 GPIO10 J1 J14 J15 R1 R2 SCL SDA
component class Skylake_TPS22993_U7: C97 C98 C99 C100 C102 C103 C106 C107 C108 L6 "ModPHY [1.0V,2.40A]" R99 R100 R101 R102 R103 R104 R105 R106 R113 R114 R115 R116 U7 "U7_V4 (1.00V)" U11 U11_PVIN
component class Skylake_TPS22993_U5_U6: C72 C73 C74 C75 C76 C78 C79 C82 C83 C84 C85 C86 C88 C89 C92 C93 C94 C95 L4 L5 R75 R76 R77 R78 R79 R80 R81 R82 R83 R84 R85 R86 R87 R88 R89 R90 R91 R92 R93 R94 R95 R96 R97 R111 R112 U5 U5_V3(3.3V) U6 U6_V3(3.3V) U10 U10_VIN "V3.3Dx_DPWP [3.3V,0.50A]" "V3.3Dx_SSD [3.3V,2.50A]" "V3.3Dx_TOUCHSCREEN [3.3V,0.20A]" "V3.3Dx_WIFI [3.3V,2.00A]" "V3.3S [3.3V,0.03A]"
component class Skylake_TPS22993_U3_U4: C46 C47 C48 C49 C50 C52 C53 C56 C57 C58 C59 C60 C61 C62 C63 C66 C67 C68 C69 C70 L2 L3 R50 R51 R52 R53 R54 R55 R56 R57 R58 R59 R60 R61 R62 R63 R64 R65 R66 R67 R68 R69 R70 R71 R72 R73 R109 R110 U3 U3_V2(3.3V) U4 U4_V2(3.3V) U9 U9_VIN "V3.3A_EC [3.3V,0.10A]" "V3.3Dx_3G4G [3.3V,2.4A]" "V3.3Dx_AUDIO [3.3V,0.20A]" "V3.3Dx_EDP [3.3V,0.75A]" "V3.3Dx_SENSORS [3.3V,0.09A]" "V3.3Dx_USBSDIO [3.3V,0.80A]" "V3.3M [3.3V,0.22A]"
component class Skylake_TPS22993_U1_U2: C21 C22 C23 C24 C26 C27 C30 C31 C32 C33 C34 C35 C36 C37 C40 C41 C42 C43 C44 C45 L1 R29 R30 R31 R32 R33 R34 R35 R36 R37 R38 R39 R40 R41 R42 R43 R44 R45 R46 R47 R48 R107 R108 U1 U1_V1(1.8V) U2 U2_V1(1.8V) U8 U8_PVIN "V1.8Dx_3G4G [1.8V,0.07A]" "V1.8Dx_AUDIO [1.8V,0.13A]" "V1.8Dx_SENSORS [1.8V,0.07A]" "V1.8Dx_SSD [1.8V,0.07A]" "V1.8Dx_USBSDIO [1.8V,0.05A]" "V1.8Dx_WIFI [1.8V,0.07A]" "V1.8M [1.8V,0.01A]" "V1.8S [1.8V,0.10A]"
component class Skylake_LEDs_2: D13 D14 D15 D16 D17 D18 D19 D20 D21 D22 D23 D24 D25 R15 R16 R17 R18 R19 R20 R21 R22 R23 R24 R25 R26 R27 U24 U25 U26 U27 U28 U29 U30 U31 U32 U33 U34 U35 U36
component class Skylake_LEDs_1: D2 D3 D4 D5 D6 D7 D8 D9 D10 D11 D12 D26 R3 R4 R5 R6 R7 R8 R9 R10 R11 R12 R13 R14 U12 U13 U14 U15 U16 U17 U18 U19 U20 U21 U22 U23
component class AssemblyNote: ZZ1 ZZ2 ZZ3 ZZ4 ZZ5 ZZ6
component class FiducialMark: FID1 FID2 FID3 FID4 FID5 FID6
component class Skylake_Hardware: BATT+ C1 C2 C3 C4 C5 C6 C7 C8 C9 C10 C11 C12 C13 C14 C15 C16 C17 C18 D1 FID1 FID2 FID3 FID4 FID5 FID6 GND H1 H2 H3 H4 H5 H6 H7 H8 J4 J5 J6 J7 J8 J9 Logo1 ZZ1 ZZ2 ZZ3 ZZ4 ZZ5 ZZ6
component class Logo: Logo1
component class "Mounting Holes": H1 H2 H3 H4

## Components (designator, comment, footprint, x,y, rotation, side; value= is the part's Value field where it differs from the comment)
+3.3V_USB "5005" Keystone5005 320,2205 r90 top
+5V_USB "5005" Keystone5005 325,2800 r90 top
BATT+ "5005" Keystone5005 2340,3285 r90 top
C1 "TPSV686M035R0150" 7361-38 1965,3200 r270 bottom
C2 "C3225X6S1V106K250AC" 1210 2175,3185 r270 bottom
C3 "C1608X7R1V105K080AC" 0805_HV 595,1030 r270 top
C4 "Taiyo Yuden" 0805_HV 3070,545 r270 top
C5 "C1608X7R1V105K080AC" 0805_HV 3450,2565 r90 top
C6 "Taiyo Yuden" 0805_HV 655.29,2880.93 r180 top
C7 "0805ZC105KAT2A" 0805_HV 350,685 r270 top
C8 "C0603C104K8RACTU" 0603 435,685 r270 top
C9 "0805ZC105KAT2A" 0805_HV 3055,280 r270 top
C10 "C0603C104K8RACTU" 0603 3140,275 r270 top
C11 "0805ZC105KAT2A" 0805_HV 3395,3580 r90 top
C12 "C0603C104K8RACTU" 0603 3480,3580 r90 top
C13 "0805ZC105KAT2A" 0805_HV 590,3360 r90 top
C14 "C0603C104K8RACTU" 0603 685,3360 r90 top
C15 "0805ZC105KAT2A" 0805_HV 540,685 r270 top
C16 "0805ZC105KAT2A" 0805_HV 3265,280 r270 top
C17 "0805ZC105KAT2A" 0805_HV 3265,3580 r90 top
C18 "0805ZC105KAT2A" 0805_HV 480,3360 r90 top
C19 "C0805C106K8PACTU" 0805_HV 343.66,2645.63 r0 top
C20 "C0805C106K8PACTU" 0805_HV 343.51,2373.96 r180 top
C21 "C2012JB1V106K085AC" 0805_HV 2529,1920 r0 top
C22 "Taiyo Yuden" 0805_HV 2369,1920 r180 top
C23 "C0603C332J3RACTU" 0603 2305,2050 r90 top
C24 "C2012X5R1V226M125AC" 0805_HV 2615,2080 r270 top
C26 "C0603C104K8RACTU" 0603 2275,2770 r90 top
C27 "GRM188C81A225KE34D" 0603 2005,2535 r180 top
C30 "GRM188C81A225KE34D" 0603 2530,2590 r0 top
C31 "GMK212BJ104KGHT" 0805_HV 2010,2625 r0 top
C32 "C0603C104K8RACTU" 0603 2150,2375 r90 top
C33 "C0603C104K8RACTU" 0603 2032.36,2702.6 r0 top
C34 "C0603C104K8RACTU" 0603 2520,2755 r180 top
C35 "C0603C104K8RACTU" 0603 2260,2340 r90 top
C36 "C0603C104K8RACTU" 0603 3075,2765 r90 top
C37 "GRM188C81A225KE34D" 0603 2823,2542 r180 top
C40 "GRM188C81A225KE34D" 0603 3294,2580 r0 top
C41 "GMK212BJ104KGHT" 0805_HV 2825,2625 r0 top
C42 "C0603C104K8RACTU" 0603 2970,2365 r90 top
C43 "C0603C104K8RACTU" 0603 2826.24,2705.76 r0 top
C44 "C0603C104K8RACTU" 0603 3285,2685 r180 top
C45 "C0603C104K8RACTU" 0603 3140,2365 r90 top
C46 "C2012JB1V226M125AC" 0805_HV 1520,1935 r270 top
C47 "C2012JB1V226M125AC" 0805_HV 1275,1930 r270 top
C48 "C0603C332J3RACTU" 0603 1365,1745 r90 top
C49 "C2012X5R1A476M125AC" 0805_HV 1480,1800 r180 top
C50 "C2012X5R1A476M125AC" 0805_HV 1225,1740 r0 top
C52 "C0603C104K8RACTU" 0603 610,1705 r180 top
C53 "GRM188C81A225KE34D" 0603 940,1405 r270 top
C56 "GRM188C81A225KE34D" 0603 865,1880 r90 top
C57 "GMK212BJ104KGHT" 0805_HV 780,1405 r90 top
C58 "C0603C104K8RACTU" 0603 1040,1400 r90 top
C59 "C0603C104K8RACTU" 0603 700,1410 r90 top
C60 "C0603C104K8RACTU" 0603 740,1910 r270 top
C61 "C0603C104K8RACTU" 0603 995,1910 r270 top
C62 "C0603C104K8RACTU" 0603 1695,1730 r180 top
C63 "GRM188C81A225KE34D" 0603 1920,1550 r270 top
C66 "C2012JB1V106K085AC" 0805_HV 1925,1980 r90 top
C67 "GMK212BJ104KGHT" 0805_HV 1831.13,1492.79 r90 top
C68 "C0603C104K8RACTU" 0603 2090,1505 r90 top
C69 "C0603C104K8RACTU" 0603 1750,1500 r90 top
C70 "C0603C105K8PACTU" 0603 2055,1985 r270 top
C72 "C2012JB1V226M125AC" 0805_HV 2525,1580 r0 top
C73 "C2012JB1V226M125AC" 0805_HV 2525,1325 r0 top
C74 "C0603C332J3RACTU" 0603 2690,1460 r180 top
C75 "C2012X5R1A476M125AC" 0805_HV 2670,1350 r90 top
C76 "C2012X5R1A476M125AC" 0805_HV 2655,1570 r270 top
C78 "C0603C104K8RACTU" 0603 3335,1885 r90 top
C79 "GRM188C81A225KE34D" 0603 3090,1675 r180 top
C82 "C2012JB1V106K085AC" 0805_HV 3580,1715 r0 top
C83 "GMK212BJ104KGHT" 0805_HV 3090,1815 r0 top
C84 "C0603C104K8RACTU" 0603 3005,1550 r0 top
C85 "C0603C104K8RACTU" 0603 3095,1895 r0 top
C86 "C0603C105K8PACTU" 0603 3539.09,1835.07 r180 top
C88 "C0603C104K8RACTU" 0603 3260,1180 r90 top
C89 "GRM188C81A225KE34D" 0603 3020,1035 r180 top
C92 "C2012JB1V106K085AC" 0805_HV 3550,945 r0 top
C93 "GMK212BJ104KGHT" 0805_HV 3020,955 r0 top
C94 "C0603C104K8RACTU" 0603 3030,865 r0 top
C95 "C0603C105K8PACTU" 0603 3370,1090 r270 top
C97 "C2012JB1V106K085AC" 0805_HV 1353,2827 r180 top
C98 "08055C104JAT2A" 0805_HV 1580,2900 r0 top
C99 "C0603C471K5RACTU" 0603 1575,2820 r0 top
C100 "LMK212BJ226MG-T" 0805_HV 1360,2625 r90 top
C102 "C0603C104K8RACTU" 0603 1025,2835 r90 top
C103 "GRM188R60J475KE19D" 0603 740,2590 r180 top
C106 "GRM188R60J475KE19D" 0603 1185,2625 r90 top
C107 "GMK212BJ104KGHT" 0805_HV 745,2670 r0 top
C108 "C0603C105K8PACTU" 0603 760,2750 r0 top
D1 "SMBJ18A-13-F" SMB 1730,3190 r270 bottom
D2 "SML312ECTT86" LED_SML 1410,3131.5 r270 top
D3 "SML312ECTT86" LED_SML 2515,3120 r270 top
D4 "SML312ECTT86" LED_SML 2680,3120 r270 top
D5 "SML312ECTT86" LED_SML 3640,3415 r180 top
D6 "SML312ECTT86" LED_SML 2855,3120 r270 top
D7 "SML312ECTT86" LED_SML 3205,3115 r270 top
D8 "SML312ECTT86" LED_SML 3035,3115 r270 top
D9 "SML312ECTT86" LED_SML 1400,440 r90 top
D10 "SML312ECTT86" LED_SML 755,440 r90 top
D11 "SML312ECTT86" LED_SML 420,1225 r180 top
D12 "SML312ECTT86" LED_SML 1075,440 r90 top
D13 "SML312ECTT86" LED_SML 2325,440 r90 top
D14 "SML312ECTT86" LED_SML 1700,440 r90 top
D15 "SML312ECTT86" LED_SML 2015,440 r90 top
D16 "SML312ECTT86" LED_SML 3628.77,3068.13 r180 top
D17 "SML312ECTT86" LED_SML 3635,3230 r180 top
D18 "SML312ECTT86" LED_SML 3780,2695 r0 top
D19 "SML312ECTT86" LED_SML 2650,440 r90 top
D20 "SML312ECTT86" LED_SML 2965,440 r90 top
D21 "SML312ECTT86" LED_SML 1070,3131.5 r270 top
D22 "SML312BCTT86" LED_SML 3510,3140 r270 top
D23 "SML312BCTT86" LED_SML 940,670 r90 top
D24 "SML312BCTT86" LED_SML 3365,485 r270 top
D25 "SML312BCTT86" LED_SML 915,3130 r270 top
D26 "SML312ECTT86" LED_SML 1230,3131.5 r270 top
FID1 "Fiducial" Fiducial10-20 205,3500 r0 top
FID2 "Fiducial" Fiducial10-20 549.78,261.16 r0 top
FID3 "Fiducial" Fiducial10-20 3400,155 r0 top
FID4 "Fiducial" Fiducial10-20 205,3500 r270 bottom
FID5 "Fiducial" Fiducial10-20 549.78,261.16 r270 bottom
FID6 "Fiducial" Fiducial10-20 3400,155 r270 bottom
GND "5006" Keystone5006 765,3700 r90 top
GPIO2 "5122" Keystone5122 175,800 r90 top
GPIO3 "5122" Keystone5122 465,3155 r90 top
GPIO4 "5122" Keystone5122 345,2515 r90 top
GPIO5 "5122" Keystone5122 680,3155 r90 top
GPIO6 "5122" Keystone5122 200,3250 r90 top
GPIO8 "5122" Keystone5122 320,1470 r90 top
GPIO9 "5122" Keystone5122 175,600 r90 top
GPIO10 "5122" Keystone5122 175,1200 r90 top
H1 "NY PMS 440 0025 PH" "NY PMS 440 0025 PH" 200,3800 r0 top locked
H2 "NY PMS 440 0025 PH" "NY PMS 440 0025 PH" 3800,3800 r0 top locked
H3 "NY PMS 440 0025 PH" "NY PMS 440 0025 PH" 200,200 r0 top locked
H4 "NY PMS 440 0025 PH" "NY PMS 440 0025 PH" 3800,200 r0 top locked
H5 "1902E" Keystone_1902E 3800,200 r180 bottom locked
H6 "1902E" Keystone_1902E 200,3800 r180 bottom locked
H7 "1902E" Keystone_1902E 200,200 r180 bottom locked
H8 "1902E" Keystone_1902E 3800,3800 r180 bottom locked
J1 "HEADER_2X15X100_RA" 2530-5002UB 140,2200 r270 bottom
J4 "SPC15363" Tenma_SPC15363 2340,3700 r0 top
J5 "SPC15354" Tenma_SPC15354 1590,3700 r0 top
J6 "HEADER_2X2" HDR_2X2 500,3770 r0 top
J7 "HEADER_2X2" HDR_2X2 3325,3770 r0 top
J8 "HEADER_1X3" HDR100_1X3 450,90 r0 top
J9 "HEADER_1X3" HDR100_1X3 3055,90 r0 top
J14 "JUMPER_2X100MIL" HDR100_1X2 345,3355 r270 top
J15 "JUMPER_2X100MIL" HDR100_1X2 345,3055 r270 top
L1 "XFL4020-222MEB" XFL4020 2500,2260 r0 top
L2 "XFL4020-102MEB" XFL4020 1660,1890 r270 top
L3 "XFL4020-102MEB" XFL4020 1135,1880 r270 top
L4 "XFL4020-102MEB" XFL4020 2570,1740 r0 top
L5 "XFL4020-102MEB" XFL4020 2575,1185 r0 top
L6 "XFL4020-102MEB" XFL4020 1420,2455 r180 top
Logo1 "Texas Instruments" TI_Stacked_Overlay_Small 2340,165 r0 top
"ModPHY [1.0V,2.40A]" "5007" Keystone5007 1060,3325 r90 top
R1 "CRCW04021K00FKED" 0402 435,2110 r90 top
R2 "CRCW04021K00FKED" 0402 320,1650 r270 top
R3 "CRCW06032K00FKEA" 0603 1230,3130 r270 bottom
R4 "CRCW06032K00FKEA" 0603 1410,3131.5 r270 bottom
R5 "CRCW06032K00FKEA" 0603 2515,3120 r270 bottom
R6 "CRCW06032K00FKEA" 0603 2680,3120 r270 bottom
R7 "CRCW06032K00FKEA" 0603 3640,3415 r180 bottom
R8 "CRCW06032K00FKEA" 0603 2855,3120 r270 bottom
R9 "CRCW06032K00FKEA" 0603 3205,3115 r270 bottom
R10 "CRCW06032K00FKEA" 0603 3035,3115 r270 bottom
R11 "CRCW06032K00FKEA" 0603 1400,440 r90 bottom
R12 "CRCW06032K00FKEA" 0603 755,440 r90 bottom
R13 "CRCW06032K00FKEA" 0603 420,1225 r180 bottom
R14 "CRCW06032K00FKEA" 0603 1075,440 r90 bottom
R15 "CRCW06032K00FKEA" 0603 2325,440 r90 bottom
R16 "CRCW06032K00FKEA" 0603 1700,440 r90 bottom
R17 "CRCW06032K00FKEA" 0603 2015,440 r90 bottom
R18 "CRCW06032K00FKEA" 0603 3628.77,3068.13 r180 bottom
R19 "CRCW06032K00FKEA" 0603 3635,3230 r180 bottom
R20 "CRCW06032K00FKEA" 0603 3770,2700 r180 bottom
R21 "CRCW06032K00FKEA" 0603 2650,440 r90 bottom
R22 "CRCW06032K00FKEA" 0603 2965,440 r90 bottom
R23 "CRCW06032K00FKEA" 0603 1130,3131.5 r270 bottom
R24 "CRCW0603300RJNEA" 0603 3510,3140 r270 bottom
R25 "CRCW0603300RJNEA" 0603 940,675 r90 bottom
R26 "CRCW0603300RJNEA" 0603 3365,485 r270 bottom
R27 "CRCW0603300RJNEA" 0603 1010,3130 r270 bottom
R29 "CRCW040210K0FKED" 0402 1915,2320 r0 top
R30 "CRCW040210K0FKED" 0402 2370,2785 r180 top
R31 "CRCW040210K0FKED" 0402 2185,2750 r0 top
R32 "CRCW040210K0FKED" 0402 1915,2265 r180 top
R33 "CRCW040210K0FKED" 0402 2370,2835 r0 top
R34 "CRCW040210K0FKED" 0402 2185,2805 r180 top
R35 "CRCW120618R0JNEA" 1206 2060,2310 r270 bottom
R36 "ERJ-14NF25R5U" 1210M 2001.02,2720 r180 bottom
R37 "ERJ-14NF13R7U" 1210M 2559,2762.2 r0 bottom
R38 "ERJ-14NF25R5U" 1210M 2540,2445 r0 bottom
R39 "CRCW040210K0FKED" 0402 3030,2325 r270 top
R40 "CRCW040210K0FKED" 0402 3170,2765 r180 top
R41 "CRCW040210K0FKED" 0402 2980,2745 r0 top
R42 "CRCW040210K0FKED" 0402 3080,2325 r90 top
R43 "CRCW040210K0FKED" 0402 3170,2820 r0 top
R44 "CRCW040210K0FKED" 0402 2980,2800 r180 top
R45 "CRCW120636R0JNEA" 1206 2890,2295 r270 bottom
R46 "ERJ-14NF25R5U" 1210M 2800,2745 r180 bottom
R47 "ERJ-14NF25R5U" 1210M 3335,2745 r0 bottom
R48 "CRCW1206180RJNEA" 1206 3310,2405 r0 bottom
R50 "CRCW040210K0FKED" 0402 1105,1360 r270 top
R51 "CRCW040210K0FKED" 0402 635,1800 r270 top
R52 "CRCW040210K0FKED" 0402 640,1610 r90 top
R53 "CRCW040210K0FKED" 0402 1160,1360 r90 top
R54 "CRCW040210K0FKED" 0402 565,1800 r90 top
R55 "CRCW040210K0FKED" 0402 580,1610 r270 top
R56 "CRM2512-JW-2R2ELF" 2512M 1005,1315 r270 bottom
R57 "CRM2512-JW-2R2ELF" 2512M 1005,990 r270 bottom
R58 "CRM2512-JW-2R2ELF" 2512M 720,1315 r270 bottom
R59 "CRM2512-JW-2R2ELF" 2512M 720,990 r270 bottom
R60 "RMCF2512JT33R0" 2512M 735,1985 r90 bottom
R61 "CRCW251236R5FKEG" 2512M 970,1995 r90 bottom
R62 "CRCW040210K0FKED" 0402 2125,1705 r0 top
R63 "CRCW040210K0FKED" 0402 1680,2105 r90 top
R64 "CRCW040210K0FKED" 0402 1625,2105 r90 top
R65 "CRCW040210K0FKED" 0402 2125,1760 r180 top
R66 "CRCW040210K0FKED" 0402 1735,2105 r270 top
R67 "CRCW040210K0FKED" 0402 1570,2105 r270 top
R68 "CRCW251215R0FKEG" 2512M 2075,1400 r270 bottom
R69 "RMCF2512FT16R5" 2512M 1720,1420 r270 bottom
R70 "PWR5322WR500JE" PWR5322 1730,855 r270 bottom
R71 "PWR5322WR500JE" PWR5322 1480,855 r90 bottom
R72 "RLP73K3AR22JTE" 2512M 1365,1240 r180 bottom
R73 "RLP73K3AR22JTE" 2512M 1240,990 r270 bottom
R75 "CRCW040210K0FKED" 0402 3255,1455 r270 top
R76 "CRCW040210K0FKED" 0402 3460,1900 r180 top
R77 "CRCW040210K0FKED" 0402 3250,1890 r0 top
R78 "CRCW040210K0FKED" 0402 3310,1455 r90 top
R79 "CRCW040210K0FKED" 0402 3460,1955 r0 top
R80 "CRCW040210K0FKED" 0402 3250,1945 r180 top
R81 "RMCF2512FT16R5" 2512M 3150,1400 r270 bottom
R82 "CRCW25123R30FKEGHP" 2512M 3100,2015 r90 bottom
R83 "CRCW25123R30FKEGHP" 2512M 2940,2015 r270 bottom
R84 "PWR5322WR500JE" PWR5322 3775,910 r90 bottom
R85 "PWR5322WR500JE" PWR5322 3775,1540 r90 bottom
R86 "2-1879021-1" SM_3 3775,2160 r90 bottom
R87 "CRCW040210K0FKED" 0402 2840.9,937.55 r270 top
R88 "CRCW040210K0FKED" 0402 3355,1185 r180 top
R89 "CRCW040210K0FKED" 0402 3155,1150 r0 top
R90 "CRCW040210K0FKED" 0402 2840,1045 r270 top
R91 "CRCW040210K0FKED" 0402 3355,1240 r0 top
R92 "CRCW040210K0FKED" 0402 3155,1205 r180 top
R93 "CRCW1206110RJNEA" 1206 3070,745 r270 bottom
R94 "A103634CT" SM_3 2710,820 r270 bottom
R95 "A103634CT" SM_3 2465,820 r90 bottom
R96 "A103634CT" SM_3 2220,860 r270 bottom
R97 "A103634CT" SM_3 1975,855 r90 bottom
R99 "CRCW040210K0FKED" 0402 940,2360 r270 top
R100 "CRCW040210K0FKED" 0402 1120,2855 r180 top
R101 "CRCW040210K0FKED" 0402 925,2810 r0 top
R102 "CRCW040210K0FKED" 0402 995,2360 r90 top
R103 "CRCW040210K0FKED" 0402 1120,2910 r0 top
R104 "CRCW040210K0FKED" 0402 925,2870 r180 top
R105 "RLP73K3AR20JTE" 2512M 755,2865 r90 bottom
R106 "RLP73K3AR22JTE" 2512M 520,2865 r270 bottom
R107 "CRCW040210K0FKED" 0402 2525,1930 r0 bottom
R108 "CRCW040210K0FKED" 0402 2575,1880 r180 bottom
R109 "CRCW040210K0FKED" 0402 1285,1740 r180 bottom
R110 "CRCW040210K0FKED" 0402 1285,1790 r0 bottom
R111 "CRCW040210K0FKED" 0402 2800,1370 r0 bottom
R112 "CRCW040210K0FKED" 0402 2800,1320 r180 bottom
R113 "CRCW040210K0FKED" 0402 1365,2810 r0 bottom
R114 "CRCW040210K0FKED" 0402 1340,2890 r270 bottom
R115 "CRCW060351K0JNEA" 0603 1595,2590 r270 top
R116 "CRCW0603200KFKEA" 0603 1595,2720 r270 top
SCL "5122" Keystone5122 320,2000 r90 top
SDA "5122" Keystone5122 320,1815 r90 top
U1 "TPS22993RLW" RLW0020A 2275,2550 r0 top
U1_V1(1.8V) "5005" Keystone5005 1565,3320 r90 top
U2 "TPS22993RLW" RLW0020A 3065,2535 r0 top
U2_V1(1.8V) "5005" Keystone5005 3405,3285 r90 top
U3 "TPS22993RLW" RLW0020A 860,1665 r90 top
U3_V2(3.3V) "5005" Keystone5005 760,670 r90 top
U4 "TPS22993RLW" RLW0020A 1915,1734.68 r90 top
U4_V2(3.3V) "5005" Keystone5005 1135,670 r90 top
U5 "TPS22993RLW" RLW0020A 3335,1670 r0 top
U5_V3(3.3V) "5005" Keystone5005 3529.03,507.84 r90 top
U6 "TPS22993RLW" RLW0020A 3260,940 r0 top
U6_V3(3.3V) "5005" Keystone5005 3533.28,287.38 r90 top
U7 "TPS22993RLW" RLW0020A 985,2580 r0 top
"U7_V4 (1.00V)" "5005" Keystone5005 890,3325 r180 top
U8 "TPS62151RGTT" RGT0016C 2435,2060 r270 top
U8_PVIN "5005" Keystone5005 2840,3600 r90 top
U9 "TPS62182YZF" YZF0024AMAM 1395,1920 r270 top
U9_VIN "5005" Keystone5005 1157.17,3854.68 r90 top
U10 "TPS62182YZF" YZF0024AMAM 2534.84,1449.85 r0 top
U10_VIN "5005" Keystone5005 3767.07,518.81 r90 top
U11 "TPS62130RGTR" RGT0016C 1484,2701 r90 top
U11_PVIN "5005" Keystone5005 1155.83,3609.95 r90 top
U12 "TPS22929DDBV" DBV-6 1915,2310 r270 bottom
U13 "TPS22929DDBV" DBV-6 2010,2890 r180 bottom
U14 "TPS22929DDBV" DBV-6 2555,2940 r0 bottom
U15 "TPS22929DDBV" DBV-6 2255,2160 r180 bottom
U16 "TPS22929DDBV" DBV-6 2750,2295 r270 bottom
U17 "TPS22929DDBV" DBV-6 2805,2920 r180 bottom
U18 "TPS22929DDBV" DBV-6 3325,2930 r0 bottom
U19 "TPS22929DDBV" DBV-6 3310,2260 r0 bottom
U20 "TPS22929DDBV" DBV-6 1270,1435 r0 bottom
U21 "TPS22929DDBV" DBV-6 550,1370 r270 bottom
U22 "TPS22929DDBV" DBV-6 515,1945 r180 bottom
U23 "TPS22929DDBV" DBV-6 1140,2090 r90 bottom
U24 "TPS22929DDBV" DBV-6 2240,1575 r90 bottom
U25 "TPS22929DDBV" DBV-6 1550,1415 r270 bottom
U26 "TPS22929DDBV" DBV-6 2170,1935 r90 bottom
U27 "TPS22929DDBV" DBV-6 2985,1410 r270 bottom
U28 "TPS22929DDBV" DBV-6 3340,2075 r90 bottom
U29 "TPS22929DDBV" DBV-6 3520,1460 r0 bottom
U30 "TPS22929DDBV" DBV-6 2929,740.69 r270 bottom
U31 "TPS22929DDBV" DBV-6 3505,780 r0 bottom
U32 "TPS22929DDBV" DBV-6 745,2350 r270 bottom
U33 "TPS22929DDBV" DBV-6 3370,3145 r180 bottom
U34 "TPS22929DDBV" DBV-6 400,1025 r270 bottom
U35 "TPS22929DDBV" DBV-6 3225,510 r90 bottom
U36 "TPS22929DDBV" DBV-6 875,3145 r90 bottom
"V1.8Dx_3G4G [1.8V,0.07A]" "5008" Keystone5008 2860,3285 r90 top
"V1.8Dx_AUDIO [1.8V,0.13A]" "5008" Keystone5008 2510,3290 r90 top
"V1.8Dx_SENSORS [1.8V,0.07A]" "5008" Keystone5008 1400,3325 r90 top
"V1.8Dx_SSD [1.8V,0.07A]" "5008" Keystone5008 2680,3290 r90 top
"V1.8Dx_USBSDIO [1.8V,0.05A]" "5008" Keystone5008 3785,3425 r90 top
"V1.8Dx_WIFI [1.8V,0.07A]" "5008" Keystone5008 3210,3285 r90 top
"V1.8M [1.8V,0.01A]" "5008" Keystone5008 3040,3285 r90 top
"V1.8S [1.8V,0.10A]" "5008" Keystone5008 1230,3325 r90 top
"V3.3A_EC [3.3V,0.10A]" "5009" Keystone5009 175,1000 r90 top
"V3.3Dx_3G4G [3.3V,2.4A]" "5009" Keystone5009 1860,425 r90 top
"V3.3Dx_AUDIO [3.3V,0.20A]" "5009" Keystone5009 1550,430 r90 top
"V3.3Dx_DPWP [3.3V,0.50A]" "5009" Keystone5009 3785,3235 r90 top
"V3.3Dx_EDP [3.3V,0.75A]" "5009" Keystone5009 600,440 r90 top
"V3.3Dx_SENSORS [3.3V,0.09A]" "5009" Keystone5009 915,440 r90 top
"V3.3Dx_SSD [3.3V,2.50A]" "5009" Keystone5009 2810,430 r90 top
"V3.3Dx_TOUCHSCREEN [3.3V,0.20A]" "5009" Keystone5009 3785,3065 r90 top
"V3.3Dx_USBSDIO [3.3V,0.80A]" "5009" Keystone5009 1240,435 r90 top
"V3.3Dx_WIFI [3.3V,2.00A]" "5009" Keystone5009 3785,2870 r90 top
"V3.3M [3.3V,0.22A]" "5009" Keystone5009 2165,430 r90 top
"V3.3S [3.3V,0.03A]" "5009" Keystone5009 2500,428.45 r90 top
ZZ1 "This Assembly Note is for PCB labels only" AssemblyNoteLabel 336.19,4833.56 r0 top
ZZ2 "These assemblies are ESD sensitive, ESD precautions shall be observed." AssemblyNote 326.19,4733.56 r0 top
ZZ3 "These assemblies must be clean and free from flux and all contaminants. Use of no clean flux is not acceptable." AssemblyNote 326.19,4653.56 r0 top
ZZ4 "These assemblies must comply with workmanship standards IPC-A-610 Class 2., unless otherwise specified." AssemblyNote 326.19,4573.56 r0 top
ZZ5 "Install TPS22994RLW at the locations U1&U2." AssemblyNote 4315,234 r90 top
ZZ6 "Install TPS22993RLW at the locations U3-U7." AssemblyNote 4077,234 r90 top

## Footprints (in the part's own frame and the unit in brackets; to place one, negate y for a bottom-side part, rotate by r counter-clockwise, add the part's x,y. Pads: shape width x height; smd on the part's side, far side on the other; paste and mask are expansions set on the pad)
0402 [mm] "0402 from SM-752 data"
  rect 0.8x0.6 smd: 1(-0.6,0) 2(0.6,0)
  silkscreen extent -1.22,-0.52 1.22,0.52, body extent -0.55,-0.3 0.55,0.3, height 0.6
0603 [mm] "0603 from SM-752 data"
  rect 1x0.95 smd: 1(-0.8,0) 2(0.8,0)
  silkscreen extent -1.52,-0.69 1.52,0.69, body extent -0.87,-0.47 0.87,0.47, height 0.85
0805_HV [mil] "0805 with 30mil clearance between pads"
  rect 50x63 smd: 1(-40,0) 2(40,0)
  silkscreen extent -74,-40 74,40, body extent -43,-29 43,29, height 43
1206 [mm] "1206 from SM-752 data"
  rect 1.3x1.85 smd: 1(-1.45,0) 2(1.45,0)
  silkscreen extent -2.4,-1.21 2.4,1.21, body extent -1.7,-0.9 1.7,0.9, height 1.35
1210 [mm] "1210 from SM-752 data"
  rect 1.3x2.7 smd: 1(-1.45,0) 2(1.45,0)
  silkscreen extent -2.32,-1.57 2.32,1.57, body extent -1.7,-1.35 1.7,1.35, height 1.35
1210M [mm] "1210 from SM-752 data"
  rect 1.5x2.8 smd: 1(-1.55,0) 2(1.55,0)
  silkscreen extent -2.75,-1.85 2.75,1.85, body extent -1.7,-1.35 1.7,1.35, height 1.35
2512M [mm] "Chip Resistor, Body 6.3x3.2mm, IPC Low Density"
  rect 1.5x3.5 smd: 1(-3.05,0) 2(3.05,0)
  silkscreen extent -1.9,-1.65 1.9,1.65, body extent -3.22,-1.67 3.22,1.67, height 0.71
2530-5002UB [mil]
  round 60 hole 40: 1(-700,50) 2(-700,-50) 3(-600,50) 4(-600,-50) 5(-500,50) 6(-500,-50) 7(-400,50) 8(-400,-50) 9(-300,50) 10(-300,-50) 11(-200,50) 12(-200,-50) 13(-100,50) 14(-100,-50) 15(0,50) 16(0,-50) 17(100,50) 18(100,-50) 19(200,50) 20(200,-50) 21(300,50) 22(300,-50) 23(400,50) 24(400,-50) 25(500,50) 26(500,-50) 27(600,50) 28(600,-50) 29(700,50) 30(700,-50)
  silkscreen extent -910,-100 910,450
7361-38 [mm] "Medium density IPC based on AVX dimensions for TPS series"
  rect 2.55x3.2 smd: 1(-2.975,0) 2(2.975,0)
  silkscreen extent -5.71,-3.2 3.75,3.2, body extent -3.75,-3.15 3.75,3.15, height 3.8
AssemblyNote [mil] "Assembly Note"
AssemblyNoteLabel [mil] "Assembly Note for PCB Labels"
DBV-6 [mil]
  rect 42x25 smd: 1(-54.5,37) 2(-54.5,0) 3(-54.5,-37) 4(54.5,-37) 5(54.5,0) 6(54.5,37)
  silkscreen extent -91,-80 91,80
Fiducial10-20 [mm]
  round 1 smd paste-0.5 mask+0.5: 1(0,0)
  TOP LAYER keep-out circle w1.178: c0,0 r0.5
HDR100_1X2 [mil]
  rect 60x60 hole 38: 1(0,0)
  round 60 hole 38: 2(100,0)
  silkscreen extent -50,-50 150,50
HDR100_1X3 [mil]
  rect 60x60 hole 38: 1(0,0)
  round 60 hole 38: 2(100,0) 3(200,0)
  silkscreen extent -50,-50 250,50
HDR_2X2 [mil]
  rect 60x60 hole 38: 1(0,0) 2(0,100) 3(100,0) 4(100,100)
  silkscreen extent -50,-50 150,150
Keystone5005 [mil] "Keystone Compact loops"
  round 87 hole 63: 1(0,0)
  silkscreen extent -70,-70 70,70, body extent -63,-63 62,63, height 225
Keystone5006 [mil] "Keystone Compact loops"
  round 87 hole 63: 1(0,0)
  silkscreen extent -70,-70 70,70, body extent -63,-63 62,63, height 225
Keystone5007 [mil] "Keystone Compact loops"
  round 87 hole 63: 1(0,0)
  silkscreen extent -70,-70 70,70, body extent -63,-63 62,63, height 225
Keystone5008 [mil] "Keystone Compact loops"
  round 87 hole 63: 1(0,0)
  silkscreen extent -70,-70 70,70, body extent -63,-63 62,63, height 225
Keystone5009 [mil] "Keystone Compact loops"
  round 87 hole 63: 1(0,0)
  silkscreen extent -70,-70 70,70, body extent -63,-63 62,63, height 225
Keystone5122 [mil] "Keystone Compact loops"
  round 87 hole 63: 1(0,0)
  silkscreen extent -70,-70 70,70, body extent -63,-63 62,63, height 225
Keystone_1902E [mil] "Hex Standoff, 4-40 threaded, nylon"
  round 1 on Mech4: 0(0,0)
  body extent -145,-126 146,126, height 1001
LED_SML [mm] "Rohm"
  rect 0.8x0.8 smd: 1(-0.825,0) 2(0.825,0)
  silkscreen extent -1.1,-0.76 1.93,0.76, body extent -0.8,-0.4 0.8,0.4, height 0.9
"NY PMS 440 0025 PH" [mm] "4-40 nylon screw and mounting hole"
  round 8 hole 3.2: 1(0,0)
  body extent -3.3,-3.3 3.3,3.3, height 2.69
PWR5322 [mm] "BOURNS"
  rect 3.7x4.2 smd: 1(-5.6,0) 2(5.6,0)
  silkscreen extent -7.1,-2.9 7.1,2.9, body extent -7.01,-2.86 7.01,2.86, height 5.88
RGT0016C [mm] "QFN, 16-Leads, Body 3x3mm, Pitch 0.5mm, Thermal Pad 1.7x1.7mm, TI Recommended"
  oval 0.85x0.28 smd paste-0.025 mask+0.013: 1(-1.475,0.75) 2(-1.475,0.25) 3(-1.475,-0.25) 4(-1.475,-0.75) 9(1.475,-0.75) 10(1.475,-0.25) 11(1.475,0.25) 12(1.475,0.75)
  oval 0.28x0.85 smd paste-0.025 mask+0.013: 5(-0.75,-1.475) 6(-0.25,-1.475) 7(0.25,-1.475) 8(0.75,-1.475) 13(0.75,1.475) 14(0.25,1.475) 15(-0.25,1.475) 16(-0.75,1.475)
  rect 1.7x1.7 smd paste-0.85 mask+0.013: 17(0,0)
  silkscreen extent -2.5,-1.73 1.73,1.73, body extent -1.57,-1.57 1.58,1.58, height 1
RLW0020A [mm] "QFN, 20-Leads, Body 3x3mm, Pitch 0.4mm, TI Recommended"
  oval 0.6x0.2 smd mask+0.045: 1(-1.4,0.8) 2(-1.4,0.4) 3(-1.4,0) 4(-1.4,-0.4) 5(-1.4,-0.8) 11(1.4,-0.8) 12(1.4,-0.4) 13(1.4,0) 14(1.4,0.4) 15(1.4,0.8)
  oval 0.2x0.6 smd mask+0.045: 6(-0.8,-1.4) 7(-0.4,-1.4) 8(0,-1.4) 9(0.4,-1.4) 10(0.8,-1.4) 16(0.8,1.4) 17(0.4,1.4) 18(0,1.4) 19(-0.4,1.4) 20(-0.8,1.4)
  rect 0.25x0.25 smd mask+0.045: 21(-1.288,1.288) 22(-1.288,-1.288) 23(1.288,-1.288) 24(1.288,1.288)
  silkscreen extent -2.22,-1.73 1.73,2.12, body extent -1.55,-1.55 1.55,1.55, height 0.81
SM_3 [mm] "TE Connectivity"
  rect 4x3.4 smd: 1(-5,0) 2(5,0)
  silkscreen extent -5.4,-2.9 5.4,2.9, body extent -5.4,-2.9 5.4,2.9, height 5.3
SMB [mil] "Molded Diode, 2-Leads, Body 5.4x3.6mm, IPC Medium Density, based on OnSemi component dimensions"
  rect 85x107.99 smd: 1(-87.01,0) 2(87.01,0)
  silkscreen extent -155,-82 125,82, body extent -106,-71 106,71, height 91
Tenma_SPC15354 [mm] "Insulated Banana Jack, Black"
  round 12 hole 6.858: 1(0,0)
  body extent -6.3,-6.34 6.35,6.34, height 8.8
Tenma_SPC15363 [mm] "Insulated Banana Jack, Red"
  round 12 hole 6.858: 1(0,0)
  body extent -6.3,-6.34 6.35,6.34, height 8.8
TI_Stacked_Overlay_Small [mil]
  silkscreen extent -418,-98 418,98
XFL4020 [mm] "Coilcraft XFL4020 7/18/12"
  rect 0.98x3.4 smd: 1(-1.181,0) 2(1.181,0)
  silkscreen extent -2.16,-2.16 2.16,2.16, body extent -2.15,-2.15 2.15,2.15, height 2.1
YZF0024AMAM [mm] "WCSP"
  round 0.275 smd paste-0.15 mask+0.05: A1(-0.75,1.25) A2(-0.25,1.25) A3(0.25,1.25) A4(0.75,1.25) B1(-0.75,0.75) B2(-0.25,0.75) B3(0.25,0.75) B4(0.75,0.75) C1(-0.75,0.25) C2(-0.25,0.25) C3(0.25,0.25) C4(0.75,0.25) D1(-0.75,-0.25) D2(-0.25,-0.25) D3(0.25,-0.25) D4(0.75,-0.25) E1(-0.75,-0.75) E2(-0.25,-0.75) E3(0.25,-0.75) E4(0.75,-0.75) F1(-0.75,-1.25) F2(-0.25,-1.25) F3(0.25,-1.25) F4(0.75,-1.25)
  silkscreen extent -1.2,1.3 -0.8,1.7, body extent -1.06,-1.56 1.06,1.56, height 0.63

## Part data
+3.3V_USB +5V_USB BATT+ U1_V1(1.8V) U2_V1(1.8V) U3_V2(3.3V) U4_V2(3.3V) U5_V3(3.3V) U6_V3(3.3V) "U7_V4 (1.00V)" U8_PVIN U9_VIN U10_VIN U11_PVIN: "Test Point, Compact, Red, TH"
C1: library part TPSV686M025R0095, "CAP, TA, 68uF, 35V, +/-20%, 0.095 ohm, SMD"
C2: library part GRM32DR61E106KA12L, "CAP, CERM, 10uF, 35V, +/-10%, X5R, 1210"
C3 C5: library part GRM21BR61E226ME44, "CAP, CERM, 1uF, 35V, +/-20%, X5R, 0805"
C4 C6 C22: library part GRM21BR61E226ME44, "CAP, CERM, 0.1uF, 35V, +/-20%, X5R, 0603"
C7 C9 C11 C13 C15 C16 C17 C18: "CAP, CERM, 1uF, 10V, +/-10%, X7R, 0805"
C8 C10 C12 C14 C26 C32 C33 C34 C35 C36 C42 C43 C44 C45 C52 C58 C59 C60 C61 C62 C68 C69 C78 C84 C85 C88 C94 C102: library part GRM188R71C104KA01D, "CAP, CERM, 0.1uF, 10V, +/-10%, X7R, 0603"
C19 C20: "CAP, CERM, 10uF, 10V, +/-10%, X5R, 0805"
C21: library part C2012X5R1E106K125AB, "CAP, CERM, 10uF, 35V, +/-10%, X5R, 0805"
C23 C48 C74: library part C0603C332K5RACTU, "CAP, CERM, 3300pF, 25V, +/-5%, X7R, 0603"
C24 C46 C47 C72 C73: library part GRM21BR61E226ME44, "CAP, CERM, 22uF, 35V, +/-20%, X5R, 0805"
C27 C30 C37 C40 C53 C56 C63 C79 C89: "CAP, CERM, 2.2uF, 10V, +/-10%, X6S, 0603"
C31 C41 C57 C67 C83 C93 C107: library part GRM21BR61E226ME44, "CAP, CERM, 0.1uF, 35V, +/-20%, X5R, 0805"
C49 C50 C75 C76: library part GRM21BR61E226ME44, "CAP, CERM, 47uF, 10V, +/-20%, X5R, 0805"
C66 C82 C92 C97: library part GRM21BR61E226ME44, "CAP, CERM, 10uF, 35V, +/-10%, X5R, 0805"
C70 C86 C95 C108: "CAP, CERM, 1uF, 10V, +/-10%, X5R, 0603"
C98: "CAP, CERM, 0.1uF, 50V, +/-5%, X7R, 0805"
C99: "CAP, CERM, 470pF, 50V, +/-10%, X7R, 0603"
C100: "CAP, CERM, 22uF, 10V, +/-20%, X5R, 0805"
C103 C106: "CAP, CERM, 4.7uF, 6.3V, +/-10%, X5R, 0603"
D1: "Diode, TVS, Uni, 18V, 600W, SMB"
D2 D3 D4 D5 D6 D7 D8 D9 D10 D11 D12 D13 D14 D15 D16 D17 D18 D19 D20 D21 D26: library part SML312WBCW1, "LED, Green, SMD"
D22 D23 D24 D25: library part SML312WBCW1, "LED, Blue, SMD"
FID1 FID2 FID3 FID4 FID5 FID6: "Fiducial mark.  There is nothing to buy or mount."
GND: "Test Point, Compact, Black, TH"
GPIO2 GPIO3 GPIO4 GPIO5 GPIO6 GPIO8 GPIO9 GPIO10 SCL SDA: "Test Point, Compact, Blue, TH"
H1 H2 H3 H4: "Machine Screw, Round, #4-40 x 1/4, Nylon, Philips panhead"
H5 H6 H7 H8: "Standoff, Hex, 1\"L #4-40 Nylon"
J1: "Header, Male 2x15-pin,  100mil spacing (36-pin strip), Right-Angle"
J4: "BANANA JACK, SOLDER LUG, RED, TH"
J5: "BANANA JACK, SOLDER LUG, BLACK, TH"
J6 J7: "Header, 2x2-pin, 100mil spacing"
J8 J9: "Header, Male 3-pin, 100mil spacing,"
J14 J15: "Header, Male 2-pin, 100mil spacing,"
L1: "Inductor, Shielded, Composite, 2.2uH, 3.7A, 0.02 ohm, SMD"
L2 L3 L4 L5 L6: "Inductor, Shielded, Composite, 1uH, 5.4A, 0.01 ohm, SMD"
Logo1: library part TI_Logo, "Texas Instrument Corporate Signature"
"ModPHY [1.0V,2.40A]": "Test Point, Compact, White, TH"
R1 R2: "RES, 1.00k ohm, 1%, 0.063W, 0402"
R3 R4 R5 R6 R7 R8 R9 R10 R11 R12 R13 R14 R15 R16 R17 R18 R19 R20 R21 R22 R23: "RES, 2.00k ohm, 1%, 0.1W, 0603"
R24 R25 R26 R27: "RES, 300 ohm, 5%, 0.1W, 0603"
R29 R30 R31 R40 R41 R42 R50 R52 R54 R64 R65 R66 R75 R76 R80 R88 R90 R92 R99 R103 R104 R108 R110 R112 R114: "RES, DNP, 1%, 0.063W, 0402"
R32 R33 R34 R39 R43 R44 R51 R53 R55 R62 R63 R67 R77 R78 R79 R87 R89 R91 R100 R101 R102 R107 R109 R111 R113: "RES, 10.0k ohm, 1%, 0.063W, 0402"
R35 R48 R93: "RES, DNP, 5%, 0.25W, 1206"
R36 R37 R38 R46 R47: library part ERJ14NF1001U, "RES, DNP, 1%, 0.5W, 1210"
R45: library part CRCW120618R0JNEA, "RES, DNP, 5%, 0.25W, 1206"
R56 R58 R59: library part CSNL2512FT2L00, "RES, DNP, 5%, 2W, 2512"
R57: library part CSNL2512FT2L00, "RES, DNP, 1%, 2W, 2512"
R60: library part CSNL2512FT2L00, "RES, DNP, 5%, 1W, 2512"
R61 R68 R69 R81: library part CSNL2512FT2L00, "RES, DNP, 1%, 1W, 2512"
R70 R71 R84 R85: "RES, DNP, 5%, 3W, 13.5x5.65x5.5mm"
R72 R73 R105 R106: library part CRCW25121K10JNEG, "RES, DNP, 5%, 2W, 2512"
R82 R83: library part CRCW25121K10JNEG, "RES, DNP, 5%, 1.5W, 2512"
R86 R94 R95 R96 R97: library part SMW31R0JT, "RES, DNP, 5%, 3W, SM_3, 10.5x5x5.5mm"
R115: "RES, 51k ohm, 5%, 0.1W, 0603"
R116: "RES, 200k ohm, 1%, 0.1W, 0603"
U1 U2 U3 U4 U5 U6 U7: "Quad Channel Load Switch with GPIO and I2C Control, RLW0020A"
U8: "Buck Step Down Regulator with 3 to 17 V Input and 1.8 V Output, -40 to 85 degC, 16-Pin QFN (RGT), Green (RoHS & no Sb/Br)"
U9 U10: library part TPS62180YZF, "4 - 17V, 6A, 2-Phase Step-Down Converter, YZF0024AMAM"
U11: "Buck Step Down Regulator with 3 to 17 V Input and 0.9 to 6 V Output, -40 to 85 degC, 16-Pin QFN (RGT), Green (RoHS & no Sb/Br)"
U12 U13 U14 U15 U16 U17 U18 U19 U20 U21 U22 U23 U24 U25 U26 U27 U28 U29 U30 U31 U32 U33 U34 U35 U36: library part TPS2292XDBV, "IC, LOW INPUT VOLTAGE LOAD SWITCH  WITH CONTROLLED TURN-ON"
"V1.8Dx_3G4G [1.8V,0.07A]" "V1.8Dx_AUDIO [1.8V,0.13A]" "V1.8Dx_SENSORS [1.8V,0.07A]" "V1.8Dx_SSD [1.8V,0.07A]" "V1.8Dx_USBSDIO [1.8V,0.05A]" "V1.8Dx_WIFI [1.8V,0.07A]" "V1.8M [1.8V,0.01A]" "V1.8S [1.8V,0.10A]": "Test Point, Compact, Orange, TH"
"V3.3A_EC [3.3V,0.10A]" "V3.3Dx_3G4G [3.3V,2.4A]" "V3.3Dx_AUDIO [3.3V,0.20A]" "V3.3Dx_DPWP [3.3V,0.50A]" "V3.3Dx_EDP [3.3V,0.75A]" "V3.3Dx_SENSORS [3.3V,0.09A]" "V3.3Dx_SSD [3.3V,2.50A]" "V3.3Dx_TOUCHSCREEN [3.3V,0.20A]" "V3.3Dx_USBSDIO [3.3V,0.80A]" "V3.3Dx_WIFI [3.3V,2.00A]" "V3.3M [3.3V,0.22A]" "V3.3S [3.3V,0.03A]": "Test Point, Compact, Yellow, TH"
ZZ1: library part AssemblyNoteLabel
ZZ2 ZZ3 ZZ4: library part AssemblyNote
ZZ5 ZZ6: library part AssemblyNote, "These assemblies must comply with workmanship standards IPC-A-610 Class 2., unless otherwise specified."

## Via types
v1: diameter 20, hole 10, TOP LAYER to BOTTOM LAYER, 742 vias
v2: diameter 19.68, hole 7.87, TOP LAYER to BOTTOM LAYER, 10 vias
